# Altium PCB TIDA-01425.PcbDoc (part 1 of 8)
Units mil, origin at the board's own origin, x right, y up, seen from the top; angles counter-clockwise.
Board outline 7000 x 3600 mil, 6 copper layers (Layer 1 - Top Layer, Layer 2 - GND, Layer 3 - Signal / PWR, Layer 4 - Signal / PWR, Layer 5 - PWR, Layer 6 - Bottom Layer), stack 60.4 mil thick; 495 components, 307 nets, 2058 pads, 1870 vias.
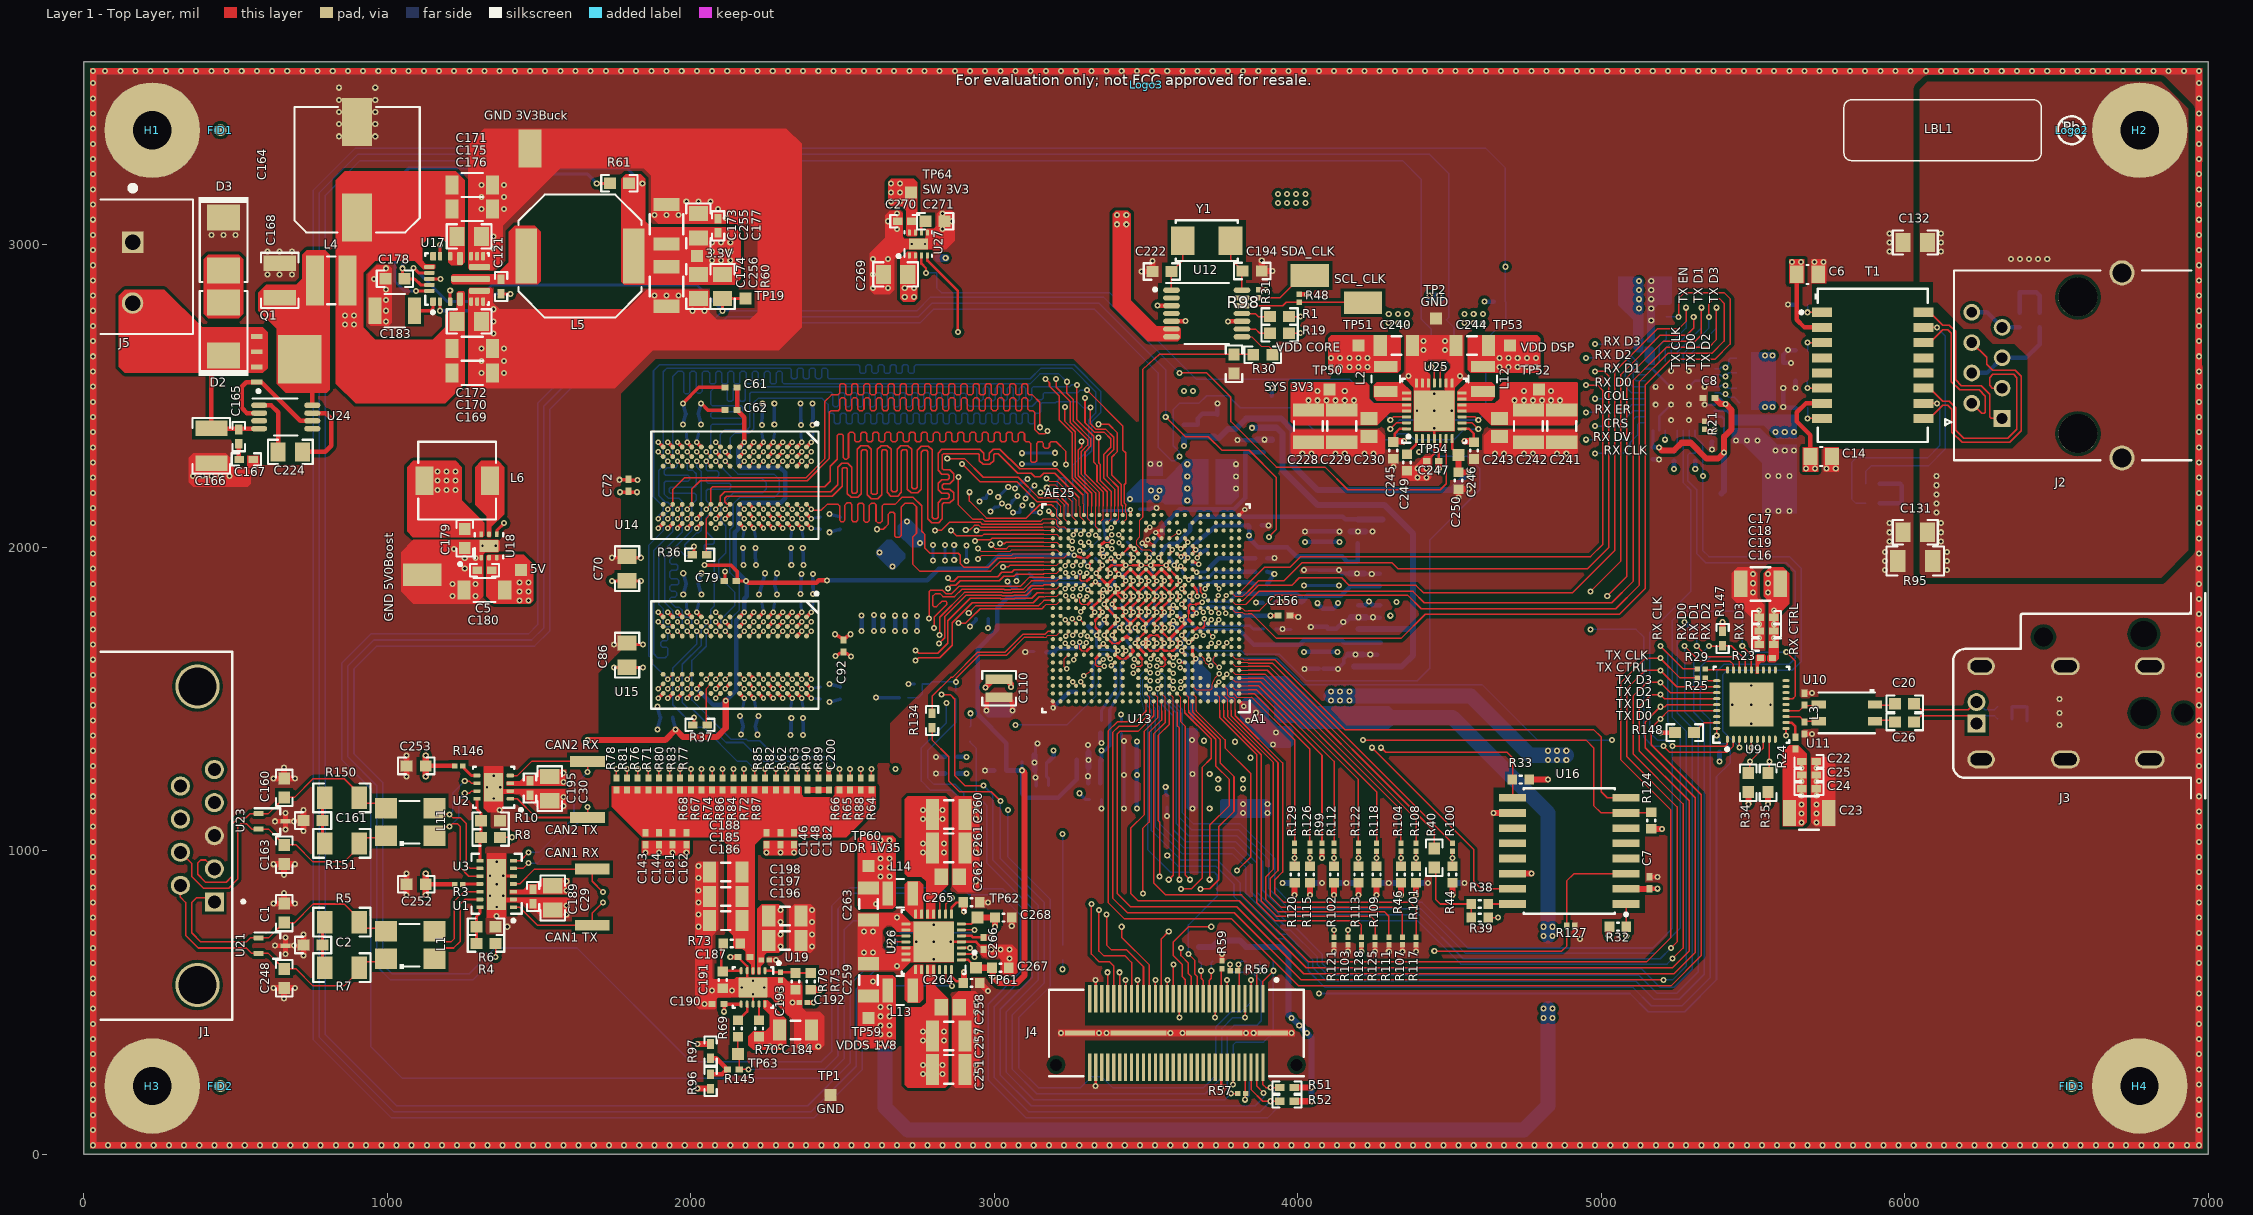
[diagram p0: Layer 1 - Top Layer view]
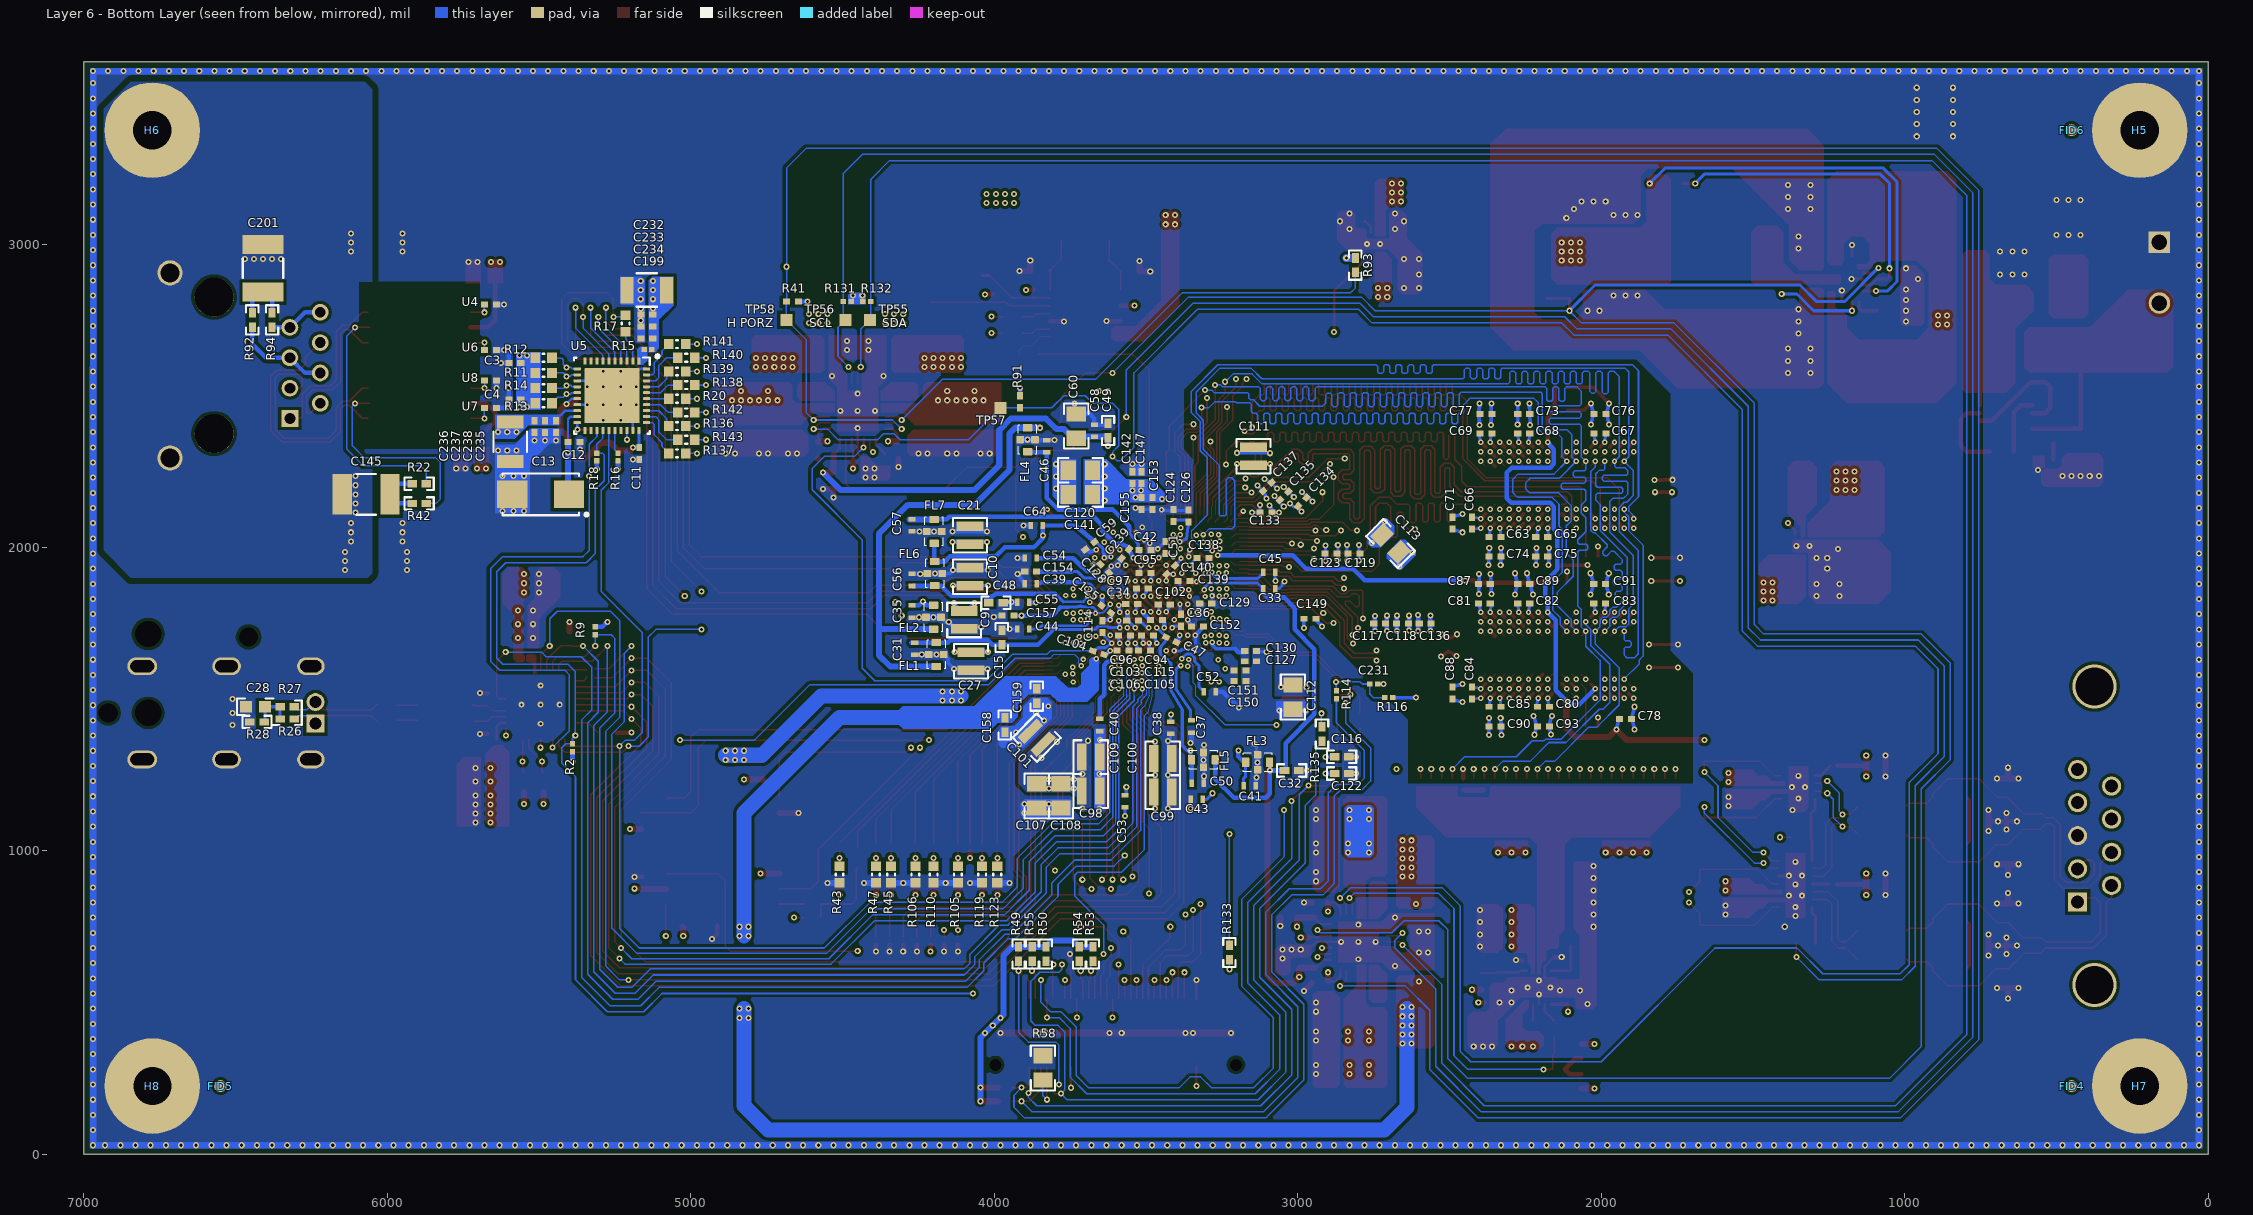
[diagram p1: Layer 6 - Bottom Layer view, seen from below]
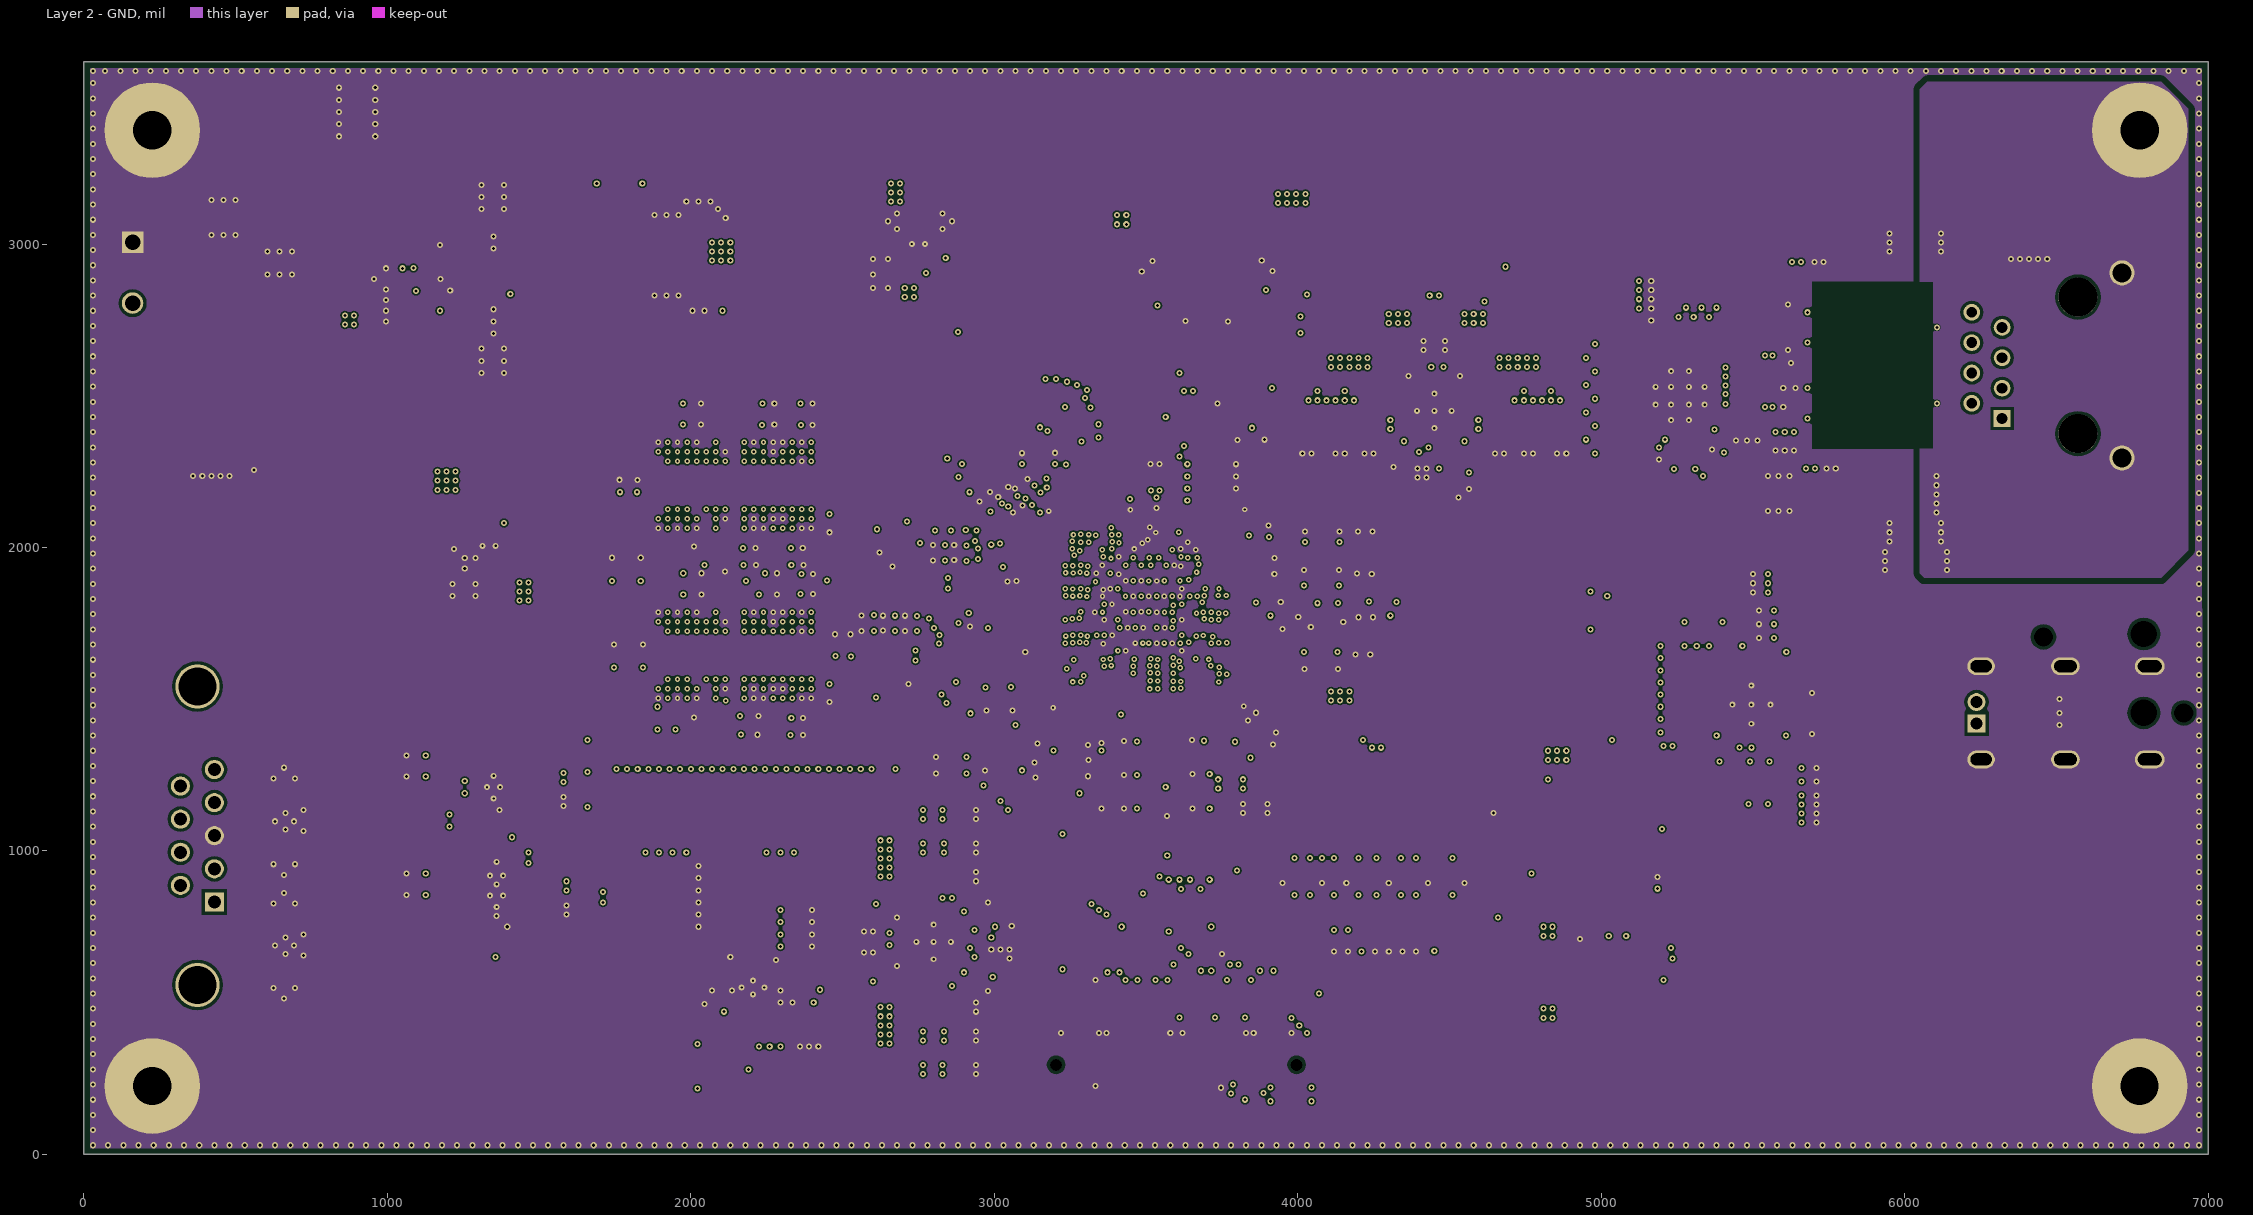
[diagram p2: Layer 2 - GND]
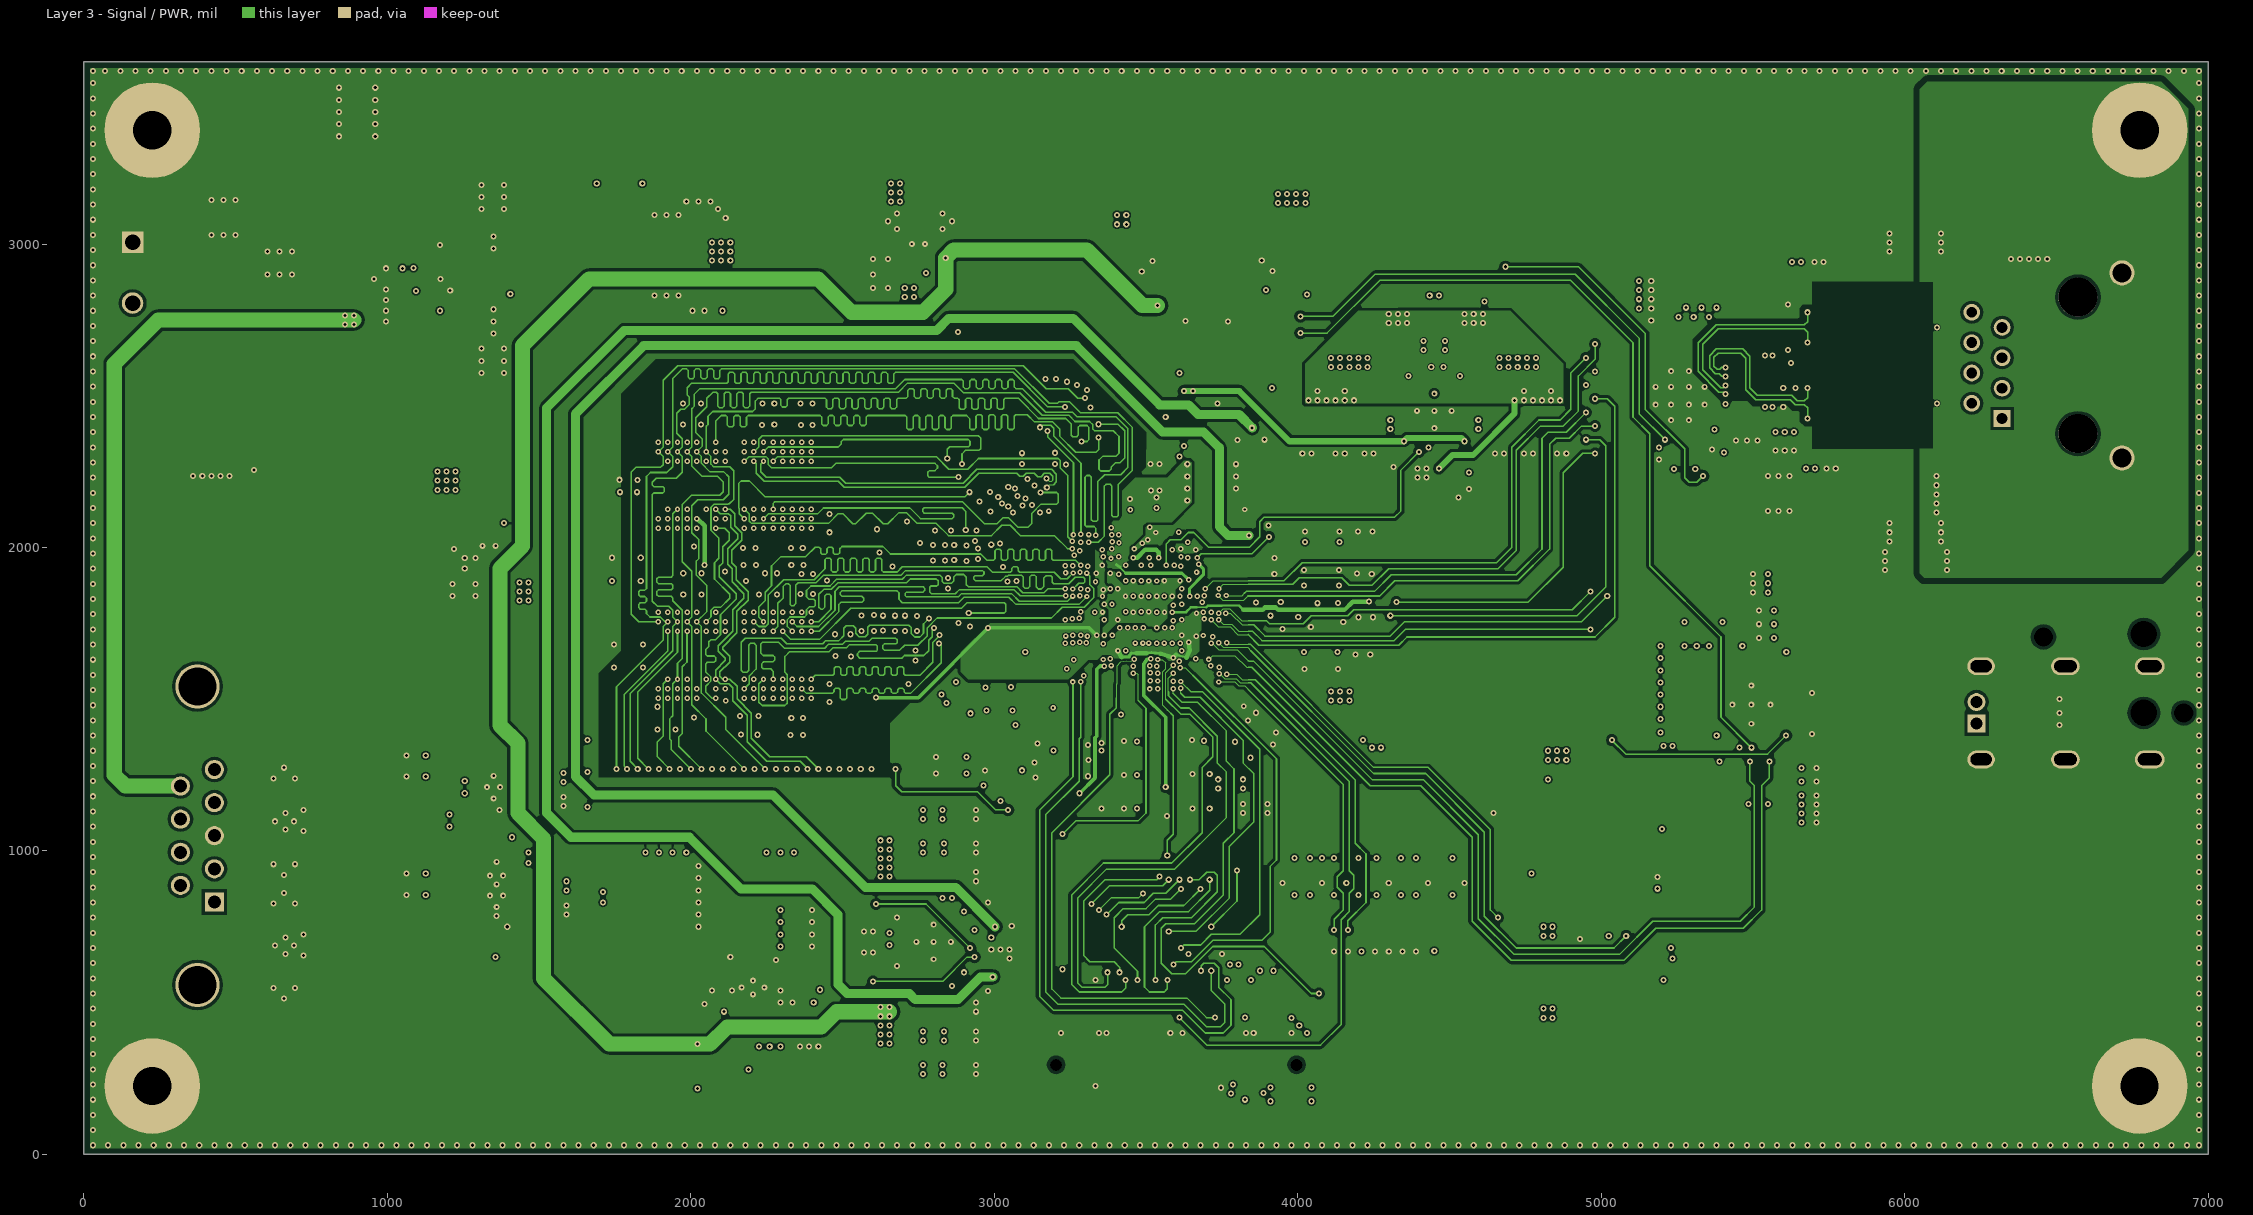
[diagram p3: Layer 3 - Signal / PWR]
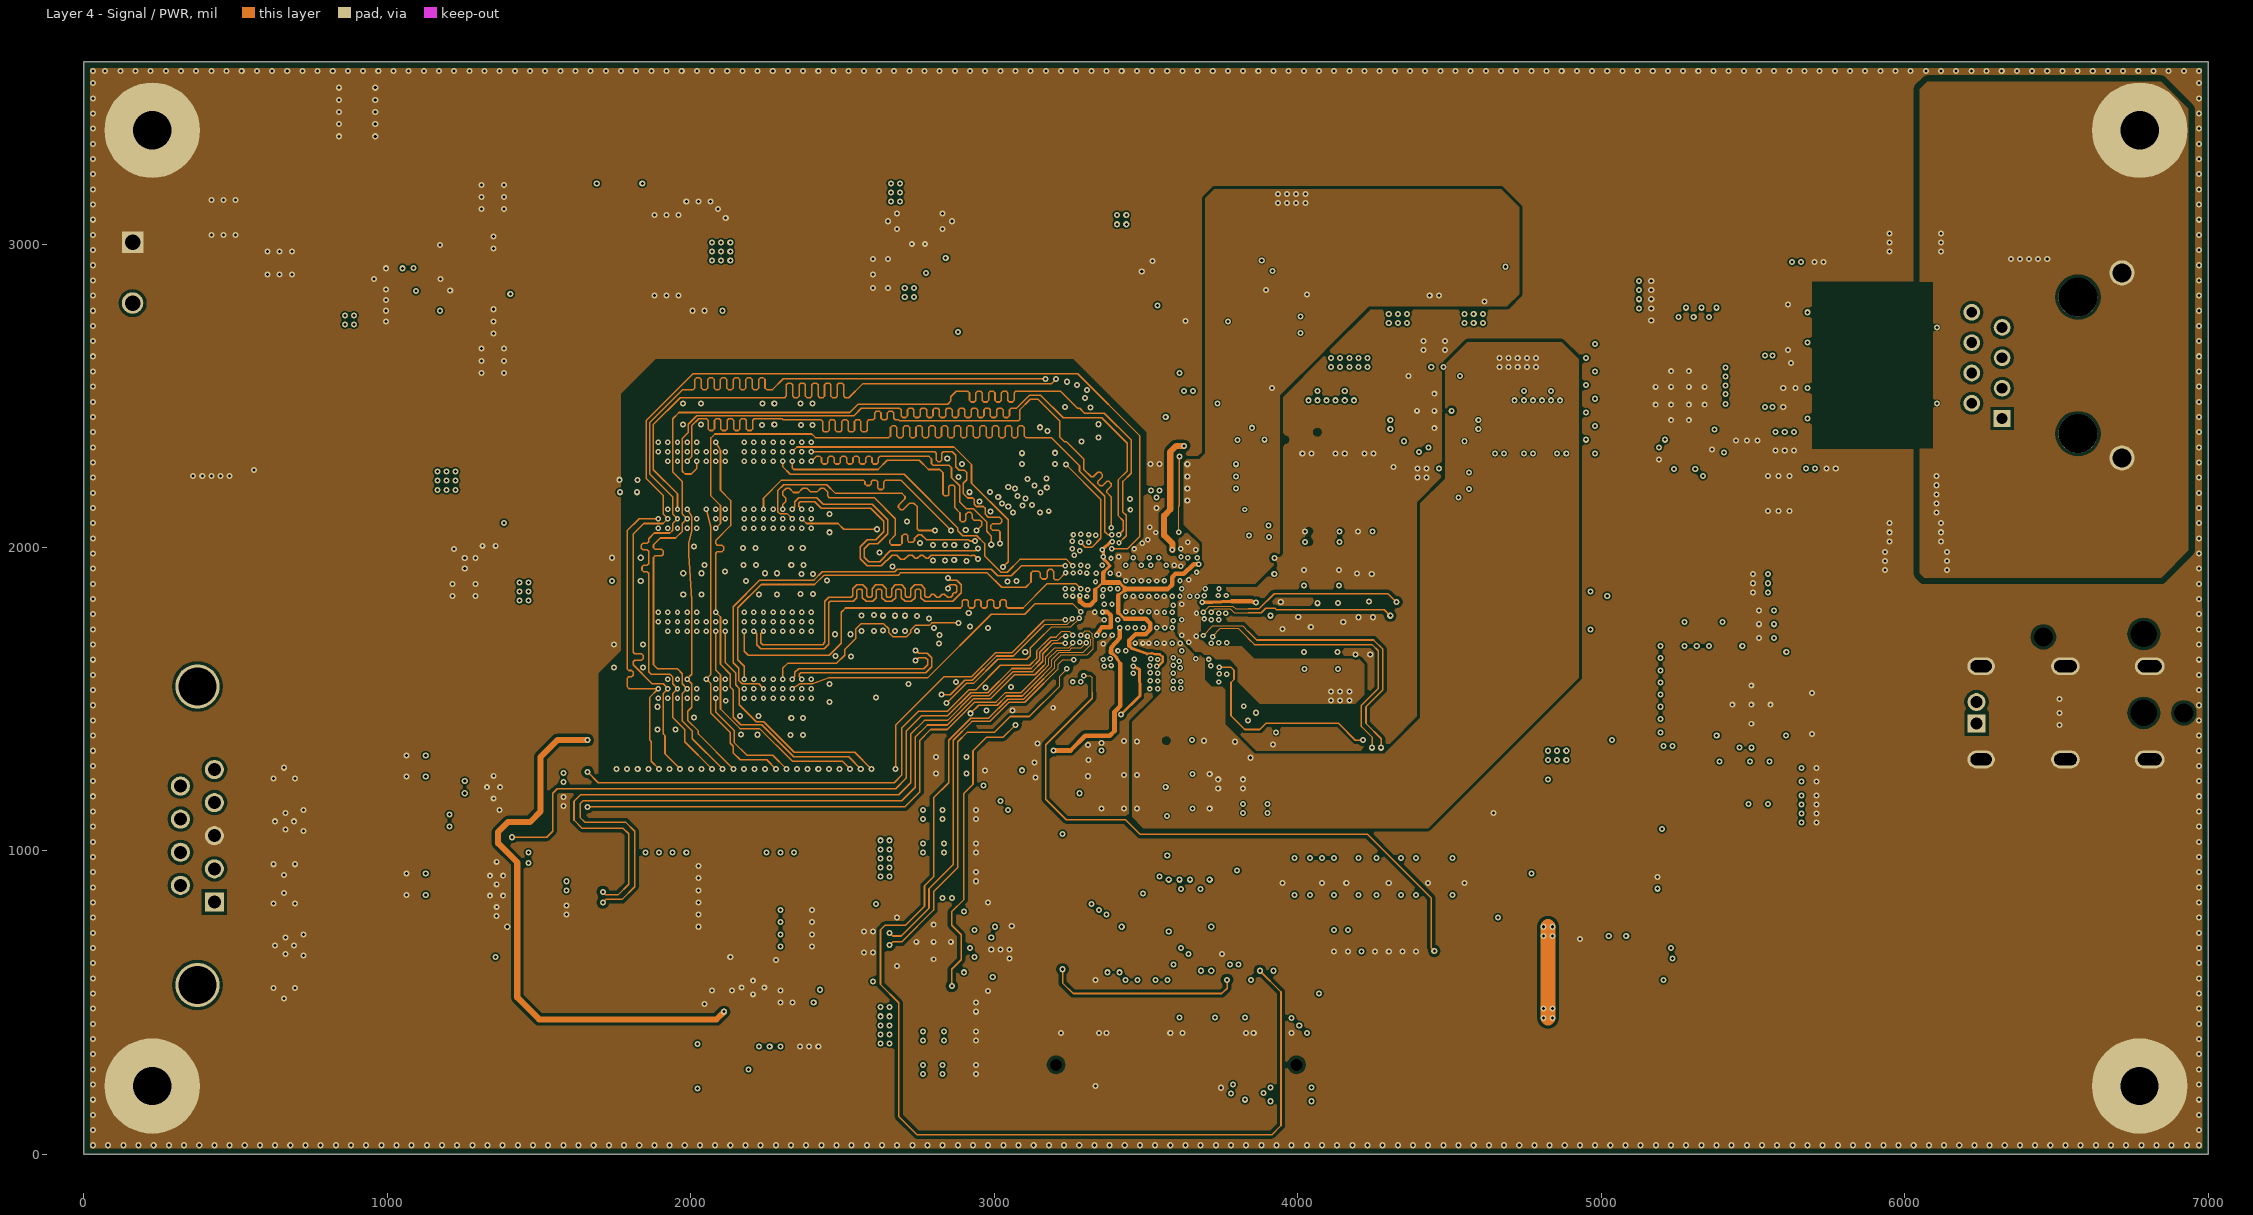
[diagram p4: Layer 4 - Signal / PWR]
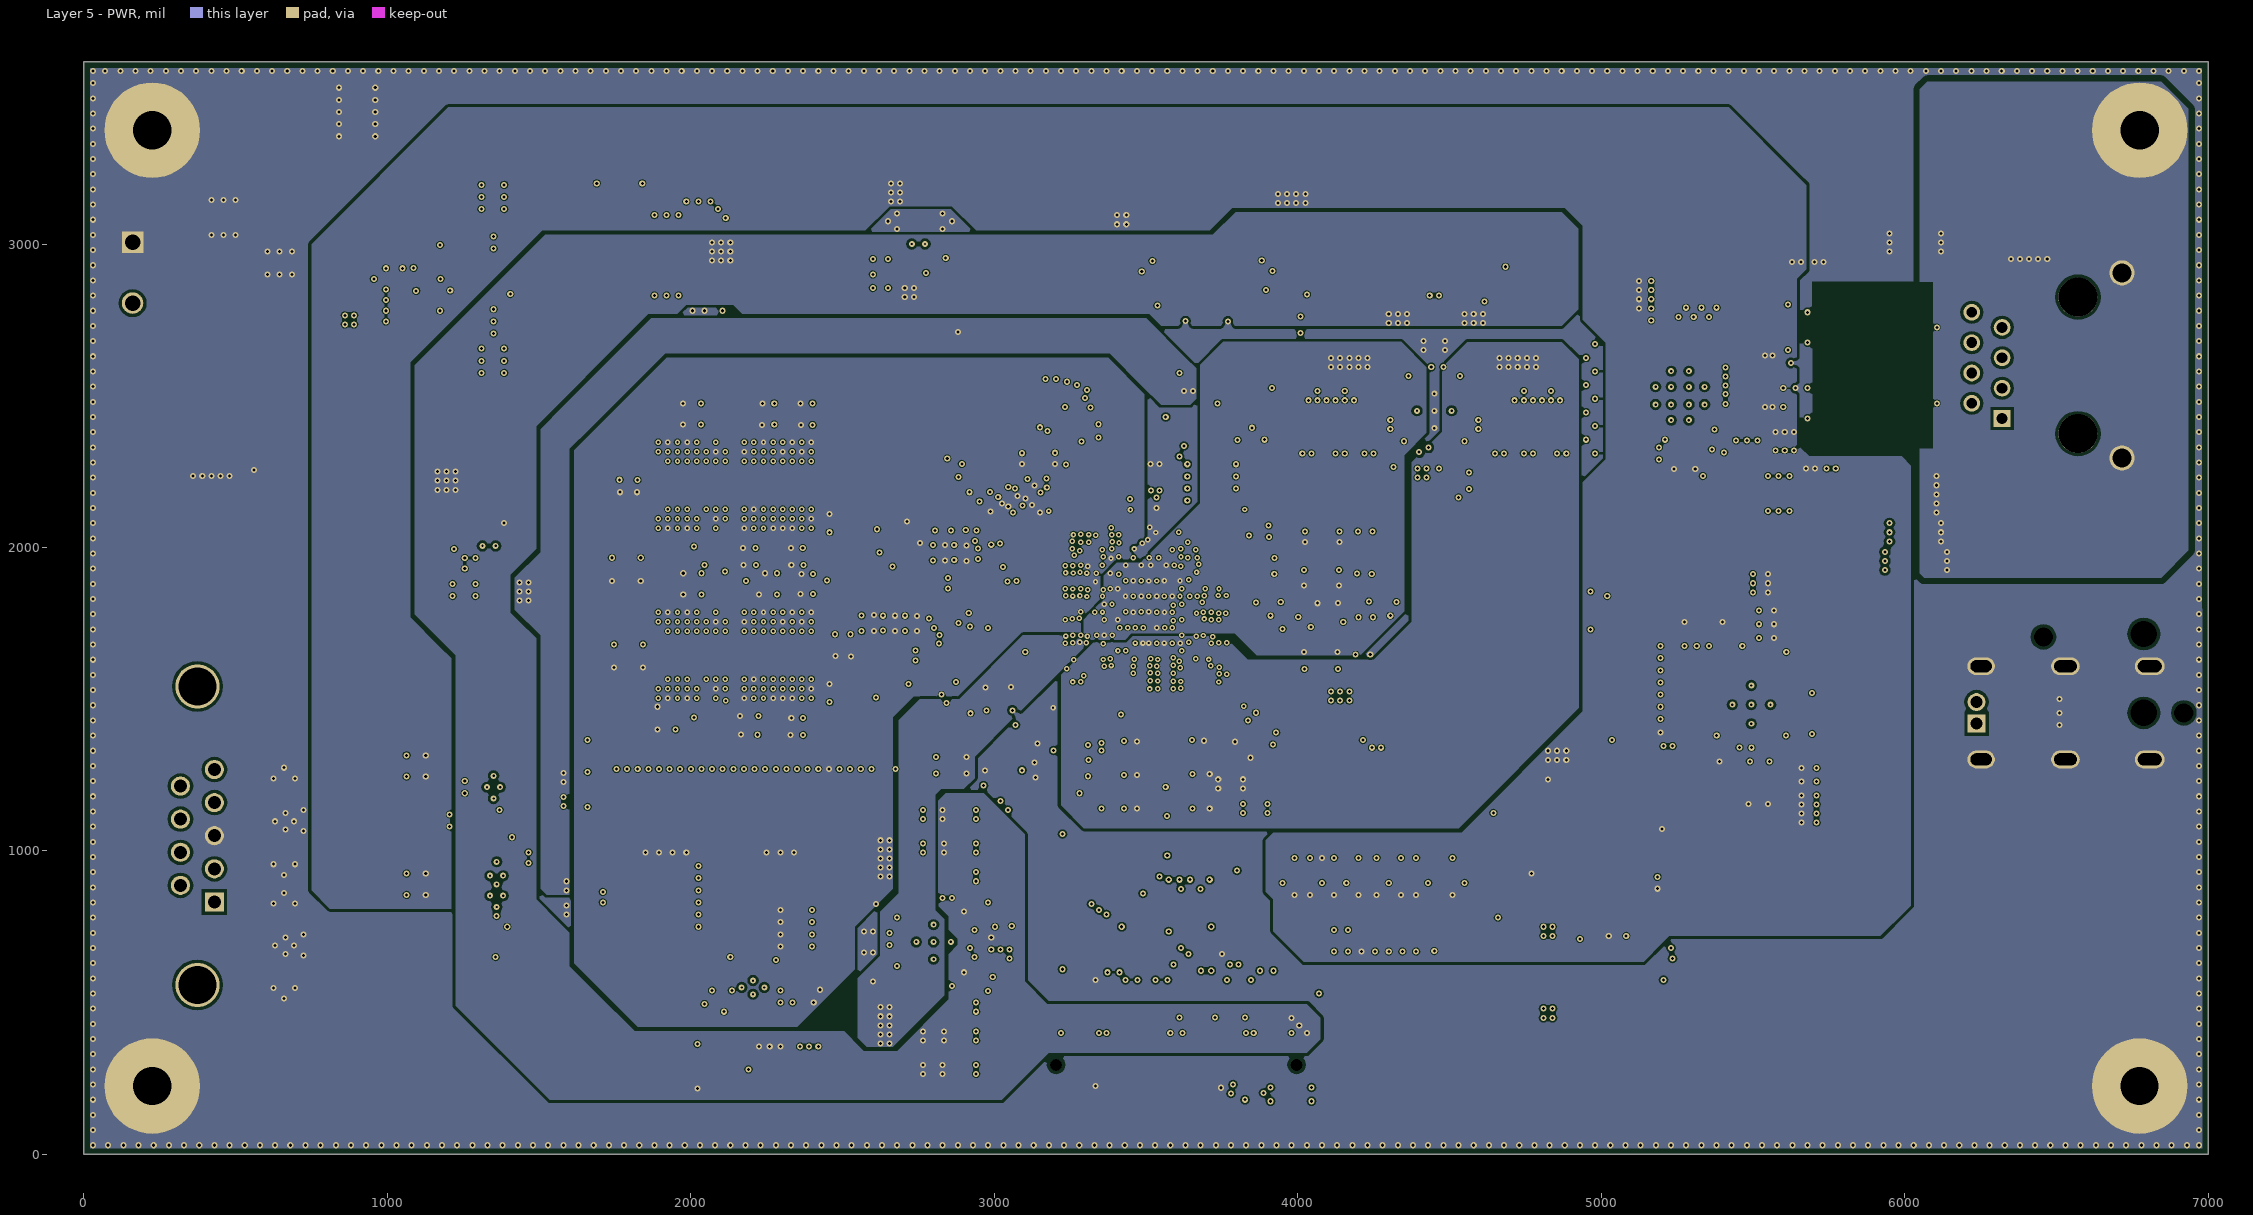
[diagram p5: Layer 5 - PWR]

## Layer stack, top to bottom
Top Solder: solder mask 0.5, Solder Resist, Dk 3.5
Layer 1 - Top Layer: signal copper 1.2
Dielectric 1: prepreg 3.4, 370H (1080HRC), Dk 4.2
Layer 2 - GND: signal copper 1.2
Dielectric 2: core 4.1, 370H (1-2116), Dk 4.2
Layer 3 - Signal / PWR: signal copper 0.6
Dielectric 3: prepreg 5.7, 370H (1080), Dk 4.2
Dielectric 4: core 28, 370H (4-7628), Dk 4.2
Dielectric 5: prepreg 5.7, 370H (1080), Dk 4.2
Layer 4 - Signal / PWR: signal copper 0.6
Dielectric 6: core 4.1, 370H (1-2116), Dk 4.2
Layer 5 - PWR: signal copper 1.2
Dielectric 7: prepreg 3.4, 370H (1080HRC), Dk 4.2
Layer 6 - Bottom Layer: signal copper 1.2
Bottom Solder: solder mask 0.5, Solder Resist, Dk 3.5

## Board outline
0,0 0,3600 7000,3600 7000,0

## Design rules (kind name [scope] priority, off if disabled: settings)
AcuteAngle [All] p1 off: minimum=4.50000000000000E+0001 checktracksonly=FALSE
AssemblyTestPointUsage [All] p1: valid=2
BoardOutlineClearance BoardOutlineClearance_MountingHoles [OnCopper and InComponentClass('Mounting Holes')] p1: gap=40 ignorepadtopadclearanceinfootprint=FALSE
BoardOutlineClearance BoardOutlineClearance_Poly [OnCopper and IsPoly] p2: gap=19 ignorepadtopadclearanceinfootprint=FALSE
BoardOutlineClearance [OnCopper and Not InComponentClass('Logo') and not InComponentClass('FiducialMark') and not InRegion(1000,500,4000,800) and not InPoly] p3: gap=19 ignorepadtopadclearanceinfootprint=FALSE
Clearance "Clearance_GND / RJ45_GND" [InNet('GND') vs InNet('RJ45 GND')] p1: gap=20 ignorepadtopadclearanceinfootprint=FALSE except(0: Arc-Hole Track-Hole SMDPad-Hole THPad-Hole Via-Hole Fill-Hole Poly-Hole Region-Hole Text-Hole)
Clearance Clearance_Poly_GND [InNet('GND') AND InPolygon] p2: gap=10 ignorepadtopadclearanceinfootprint=FALSE except(0: Arc-Hole Track-Hole SMDPad-Hole THPad-Hole Via-Hole Fill-Hole Poly-Hole Region-Hole Text-Hole)
Clearance Clearance_Keepouts [((IsTrack Or IsArc) And Not InPoly) And IsFree and IsKeepOut vs ((IsTrack Or IsArc) And Not InPoly) And IsFree and IsKeepOut] p3: gap=0 ignorepadtopadclearanceinfootprint=FALSE
Clearance Clearance_Poly [InPolygon] p4: gap=4 ignorepadtopadclearanceinfootprint=FALSE except(0: Arc-Hole Track-Hole SMDPad-Hole THPad-Hole Via-Hole Fill-Hole Poly-Hole Region-Hole Text-Hole; 8: Via-Poly; 10: Arc-Poly Track-Poly SMDPad-Poly THPad-Poly Fill-Poly Poly-Poly Poly-Region)
Clearance [All] p5: gap=3.75 ignorepadtopadclearanceinfootprint=FALSE except(0: Arc-Hole Track-Hole SMDPad-Hole THPad-Hole Via-Hole Fill-Hole Poly-Hole Region-Hole Text-Hole)
ComponentClearance "ComponentClearance_U1 / U3" [InComponent('U1') vs InComponent('U3')] p1: gap=0 collisioncheckmode=3 verticalgap=0 showdistances=FALSE
ComponentClearance ComponentClearance_MountingHoles_FiducialMarks [InComponentClass('Mounting Holes') vs InComponentClass('FiducialMark')] p2: gap=50 collisioncheckmode=3 verticalgap=10 showdistances=FALSE
ComponentClearance ComponentClearance_Shunt [InComponentClass('Header') vs InComponentClass('Shunt')] p3: gap=0 collisioncheckmode=3 verticalgap=0 showdistances=FALSE
ComponentClearance ComponentClearance_Logo [InComponentClass('Logo')] p4: gap=20 collisioncheckmode=3 verticalgap=10 showdistances=FALSE
ComponentClearance ComponentClearance_ScrewToNut [(HasFootprint('NY PMS 440 0025 PH')) vs (HasFootprint('Keystone_1902E'))] p5: gap=5 collisioncheckmode=3 verticalgap=10 showdistances=FALSE
ComponentClearance ComponentClearance_MountingHoles [InComponentClass('Mounting Holes')] p6: gap=40 collisioncheckmode=3 verticalgap=100000 showdistances=FALSE
ComponentClearance ComponentClearance_SmallPassives [HasFootprint('0201*') or HasFootprint('0402*') or HasFootprint('0508') or HasFootprint('0603*') or HasFootprint('0612') or HasFootprint('0805*') or HasFootprint('0815*') or HasFootprint('0830*') or HasFootprint('1206*') or HasFootprint('1210*') or HasFootprint('1808*') or HasFootprint('1812*') or HasFootprint('1825*') or HasFootprint('2010*') or HasFootprint('2220*') or HasFootprint('2225*') or HasFootprint('2512*') or HasFootprint('2728*') or HasFootprint('3518*') vs HasFootprint('0201*') or HasFootprint('0402*') or HasFootprint('0508') or HasFootprint('0603*') or HasFootprint('0612') or HasFootprint('0805*') or HasFootprint('0815*') or HasFootprint('0830*') or HasFootprint('1206*') or HasFootprint('1210*') or HasFootprint('1808*') or HasFootprint('1812*') or HasFootprint('1825*') or HasFootprint('2010*') or HasFootprint('2220*') or HasFootprint('2225*') or HasFootprint('2512*') or HasFootprint('2728*') or HasFootprint('3518*')] p7: gap=3.7 collisioncheckmode=3 verticalgap=10 showdistances=FALSE
ComponentClearance ComponentClearance_THtoSMT [IsThruComponent vs IsSMTComponent] p8: gap=20 collisioncheckmode=3 verticalgap=30 showdistances=FALSE
ComponentClearance ComponentClearance_THtoTH [IsThruComponent vs IsThruComponent] p9: gap=20 collisioncheckmode=3 verticalgap=30 showdistances=FALSE
ComponentClearance [All] p10: gap=3.7 collisioncheckmode=3 verticalgap=10 showdistances=FALSE
DiffPairsRouting [All] p1: maxlimit=100 minlimit=10 mostfreqgap=10 toplayer_minwidth=15 toplayer_maxwidth=15 toplayer_prefwidth=15 midlayer1_minwidth=15 midlayer1_maxwidth=15 midlayer1_prefwidth=15 midlayer2_minwidth=15 midlayer2_maxwidth=15 midlayer2_prefwidth=15 midlayer3_minwidth=15 midlayer3_maxwidth=15 midlayer3_prefwidth=15 midlayer4_minwidth=15 midlayer4_maxwidth=15 midlayer4_prefwidth=15 bottomlayer_minwidth=15 bottomlayer_maxwidth=15 bottomlayer_prefwidth=15 maxuncoupledlength=1000
FabricationTestPointUsage TestPointUsage [All] p1: valid=2 allowmultiple=FALSE
FabricationTestpoint Testpoint [All] p1: side=3 testpointundercomponent=TRUE minsize=40 maxsize=100 preferedsize=60 minholesize=0 maxholesize=40 preferedholesize=32 testpointgrid=1 allowsidetop=TRUE allowsidebottom=TRUE usegrid=TRUE gridtolerance=0.01
FanoutControl Fanout_LCC [IsLCC] p1: bgadir=Out bgaviamode=Centered fanoutstyle=Auto fanoutdirection=Alternating viagrid=1 // Fanout_LCC (Default Rule)
FanoutControl Fanout_BGA [IsBGA] p2: bgadir=Out bgaviamode=Centered fanoutstyle=Auto fanoutdirection=Alternating viagrid=1 // Fanout_BGA (Default Rule)
FanoutControl Fanout_Default [All] p4: bgadir=Out bgaviamode=Centered fanoutstyle=Auto fanoutdirection=Alternating viagrid=1 // Fanout_Default (Default Rule)
FanoutControl Fanout_Small [(CompPinCount < 5)] p5: bgadir=Out bgaviamode=Centered fanoutstyle=Auto fanoutdirection=OutThenIn viagrid=1 // Fanout_Small (Default Rule)
Height [All] p1: minheight=0 maxheight=1001 prefheight=500
HoleSize [All] p1: absolutevalues=TRUE maxlimit=251 minlimit=7.87 maxpercent=80.000 minpercent=20.000
MinimumAnnularRing MinimumAnnularRing_ThermalPadVias [IsVia and InAnyComponent] p1: minimumring=5.91
MinimumAnnularRing [All] p2 off: minimumring=5
MinimumSolderMaskSliver MinimumSolderMaskSliver_Logo [InComponentClass('Logo') vs InComponentClass('Logo')] p1: minsoldermaskwidth=0.7
MinimumSolderMaskSliver [All] p2: minsoldermaskwidth=0.9
PlaneConnect [All] p1: planeconnectstyle=Relief reliefexpansion=10 reliefentries=4 reliefconductorwidth=10 reliefairgap=10
PolygonConnect [All] p1: connectstyle=Direct reliefconductorwidth=10 reliefentries=4 polygonreliefangle="90 Angle" airgapwidth=10
RoutingVias ThermalPadVias [IsVia and InAnyComponent] p1: holewidth=7.87 width=19.68 viastyle="Through Hole" minholewidth=7.87 minwidth=19.68 maxholewidth=12.99 maxwidth=23.62
RoutingVias [All] p2: holewidth=16 width=20 viastyle="Through Hole" minholewidth=7.87 minwidth=18 maxholewidth=40 maxwidth=65
SilkToBoardRegionClearance [Not ((IsComment or IsDesignator) And (Hide <> 'False')) and not InRegion(1000,500,4000,800)] p1:
SilkToSilkClearance SilkToSilkClearance_Pb-FreeLogo [(HasFootprint('Pb-Free_Overlay_Medium') OR HasFootprint('Pb-Free_Overlay_Small')) vs (HasFootprint('Pb-Free_Overlay_Medium') OR HasFootprint('Pb-Free_Overlay_Small'))] p1: silktosilkclearance=0
SilkToSilkClearance [All] p2: silktosilkclearance=4
SilkToSolderMaskClearance "SilkToSolderMaskClearance_TI LOGO" [HasFootprint('TI_Stacked_Overlay_Small')] p1: minsilkscreentomaskgap=0 clearancetoexposedcopper=TRUE
SilkToSolderMaskClearance SilkToComponentPadClearance [(IsPad or IsFill or IsRegion) and InAnycomponent] p2 off: minsilkscreentomaskgap=3.5 clearancetoexposedcopper=TRUE
SilkToSolderMaskClearance "Silk to Solder Mask Opening" [All] p3 off: minsilkscreentomaskgap=4 clearancetoexposedcopper=FALSE
SolderMaskExpansion [All] p1: expansion=1.97
Width [All] p1: maxlimit=100 minlimit=4 preferedwidth=10 checkconnectedcopper=TRUE
14 further rules are at their usual default settings.

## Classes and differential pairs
component class JTAG: J4 R49 R50 R51 R52 R53 R54 R55 R56 R57 R58 R59
component class J6Entry: C7 C194 C222 C231 R1 R19 R30 R31 R32 R33 R38 R39 R40 R43 R44 R45 R46 R47 R48 R98 R99 R100 R101 R102 R103 R104 R105 R106 R107 R108 R109 R110 R111 R112 R113 R114 R115 R116 R117 R118 R119 R120 R121 R122 R123 R124 R125 R126 R127 R128 R129 R131 R132 R133 R134 R135 SCL_CLK SDA_CLK U12 U13 U16 Y1
component class "J6E DDR": C143 C144 C146 C148 C162 C181 C182 C184 C185 C186 C187 C188 C190 C191 C192 C193 C196 C197 C198 C200 R62 R63 R64 R65 R66 R67 R68 R69 R70 R71 R72 R73 R74 R75 R76 R77 R78 R79 R80 R81 R82 R83 R84 R85 R86 R87 R88 R89 R90 U19
component class Ethernet_subsystem: C3 C4 C6 C8 C11 C12 C13 C14 C16 C17 C18 C19 C20 C22 C23 C24 C25 C26 C28 C131 C132 C145 C199 C201 C232 C233 C234 C235 C236 C237 C238 J2 J3 L3 R2 R9 R11 R12 R13 R14 R15 R16 R17 R18 R20 R21 R22 R23 R24 R25 R26 R27 R28 R29 R34 R35 R42 R92 R94 R95 R136 R137 R138 R139 R140 R141 R142 R143 R147 R148 T1 U4 U5 U6 U7 U8 U9 U10 U11
component class "DIG PWR": C9 C10 C21 C27 C94 C95 C96 C97 C98 C99 C100 C101 C102 C103 C104 C105 C106 C107 C108 C109 C110 C111 C112 C113 C114 C115 C116 C117 C118 C119 C120 C122 C123 C124 C125 C126 C127 C128 C129 C130 C133 C134 C135 C136 C137 C138 C139 C140 C141 C142 C147 C149 C150 C151 C152 C153 C154 C155 C156 C157 C158 C159
component class DDR3: C61 C62 C63 C65 C66 C67 C68 C69 C70 C71 C72 C73 C74 C75 C76 C77 C78 C79 C80 C81 C82 C83 C84 C85 C86 C87 C88 C89 C90 C91 C92 C93 R36 R37 U14 U15
component class "DCDC PWR": 3.3V 5V C5 C121 C164 C165 C166 C167 C168 C169 C170 C171 C172 C173 C174 C175 C176 C177 C178 C179 C180 C183 C224 C255 C256 D2 D3 "GND 3V3Buck" "GND 5V0Boost" J5 L4 L5 L6 Q1 R60 R61 TP19 U17 U18 U24
component class CAN_subsystem2.0: C1 C2 C29 C30 C160 C161 C163 C189 C195 C248 C252 C253 "CAN1 RX" "CAN1 TX" "CAN2 RX" "CAN2 TX" J1 L1 L11 R3 R4 R5 R6 R7 R8 R10 R146 R150 R151 U1 U2 U3 U21 U23
component class "ANA PWR": C15 C31 C32 C33 C34 C35 C36 C37 C38 C39 C40 C41 C42 C43 C44 C45 C46 C47 C48 C49 C50 C51 C52 C53 C54 C55 C56 C57 C58 C59 C60 C64 C239 FL1 FL2 FL3 FL4 FL5 FL6 FL7
component class Label: LBL1
component class AssemblyNote: ZZ1 ZZ2 ZZ3 ZZ4
component class FiducialMark: FID1 FID2 FID3 FID4 FID5 FID6
component class TIDA-01425_EVM_Hardware: FID1 FID2 FID3 FID4 FID5 FID6 H1 H2 H3 H4 H5 H6 H7 H8 LBL1 Logo2 Logo3 ZZ1 ZZ2 ZZ3 ZZ4
component class "Mounting Holes": H1 H2 H3 H4
component class "LP873x (PMIC)": C228 C229 C230 C240 C241 C242 C243 C244 C245 C246 C247 C249 C250 C251 C257 C258 C259 C260 C261 C262 C263 C264 C265 C266 C267 C268 C269 C270 C271 L2 L12 L13 L14 R41 R91 R93 R96 R97 R145 TP1 TP2 TP50 TP51 TP52 TP53 TP54 TP55 TP56 TP57 TP58 TP59 TP60 TP61 TP62 TP63 TP64 U25 U26 U27

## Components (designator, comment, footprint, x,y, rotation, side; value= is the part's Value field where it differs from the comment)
3.3V "PAD_1MM_SQUARE" PAD_1MM_SQUARE 2020,2960 r90 top
5V "PAD_1MM_SQUARE" PAD_1MM_SQUARE 1440,1925 r90 top
C1 "GRM1885C1H560JA01D" 0603 660,795 r90 top value=56pF
C2 "GCM188R71H472KA37D" 0603 755,690 r180 top value=4700pF
C3 "0402ZC103KAT2A" 0402L 5580,2608 r0 bottom value=0.01uF
C4 "0402ZC103KAT2A" 0402L 5580,2488 r0 bottom value=0.01uF
C5 "GRM155R71C104JA88D" 0402 1320,1925 r180 top value=0.1uF
C6 "CEU4J2X7R1H104K125AE" 0805_150 5680,2900 r0 top value=0.1uF
C7 "0402ZC103KAT2A" 0402L 5160,895 r90 top value=0.01uF
C8 "C0402C104K4RACAUTO" 0402L 5355,2493 r0 top value=0.1uF
C9 "LLL219R70J105MA01L" 0508 4099,1761 r270 bottom value=1uF
C10 "LLL219R70J105MA01L" 0508 4080,1903 r90 bottom value=1uF
C11 "C0402C104K4RACAUTO" 0402L 5170,2310 r90 bottom value=0.1uF
C12 "C0402C104K4RACAUTO" 0402L 5385,2348 r0 bottom value=0.1uF
C13 "293D106X9010C2TE3" 6032-28 5495,2175 r0 bottom value=10uF
C14 "CEU4J2X7R1H104K125AE" 0805_150 5725,2300 r180 top value=0.1uF
C15 "GRM155R71C104KA88D" 0402 3975,1703 r90 bottom value=0.1uF
C16 "CGA2B2C0G1H101J050BA" 0402 5545,1680 r180 top value=100pF
C17 "CGA6P1X7R1E106M250AC" 1210_280 5525,1880 r180 top value=10uF
C18 "CGA2B3X7R1H103K050BB" 0402 5545,1770 r180 top value=0.01uF
C19 "CGA2B2C0G1H102J050BA" 0402 5545,1725 r180 top value=1000pF
C20 "06035C104KAT2A" 0603 6000,1485 r180 top value=0.1uF
C21 "LLL219R70J105MA01L" 0508 4080,2040 r90 bottom value=1uF
C22 "CGA2B2C0G1H101J050BA" 0402 5685,1295 r0 top value=100pF
C23 "CGA6P1X7R1E106M250AC" 1210_280 5685,1125 r0 top value=10uF
C24 "CGA2B3X7R1H103K050BB" 0402 5685,1205 r0 top value=0.01uF
C25 "CGA2B2C0G1H102J050BA" 0402 5685,1250 r0 top value=1000pF
C26 "06035C104KAT2A" 0603 6000,1425 r180 top value=0.1uF
C27 "LLL219R70J105MA01L" 0508 4077,1625 r270 bottom value=1uF
C28 "C0603C472K5RACTU" 0603 6435,1475 r0 bottom value=4700pF
C29 "C2012X7R1A475M125AC" 0805_HV 1545,845 r270 top value=4.7uF
C30 "C2012X7R1A475M125AC" 0805_HV 1535,1205 r270 top value=4.7uF
C31 "GCM155C71A105KE38D" 0402_070 4262,1666 r270 bottom value=1uF
C32 "GRM155R71C104KA88D" 0402 3020,1265 r180 bottom value=0.1uF
C33 "GCM155C71A105KE38D" 0402_070 3094,1864 r180 bottom value=1uF
C34 "GRM155R71C104KA88D" 0402L 3547,1813 r180 bottom value=0.1uF
C35 "GCM155C71A105KE38D" 0402_070 4271,1789 r270 bottom value=1uF
C36 "GRM155R71C104KA88D" 0402L 3385,1760 r90 bottom value=0.1uF
C37 "GCM155C71A105KE38D" 0402_070 3350,1410 r270 bottom value=1uF
C38 "GCM155C71A105KE38D" 0402_070 3418.35,1406 r270 bottom value=1uF
C39 "GCM155C71A105KE38D" 0402_070 3880,1880 r0 bottom value=1uF
C40 "GCM155C71A105KE38D" 0402_070 3652,1415 r270 bottom value=1uF
C41 "GCM155C71A105KE38D" 0402_070 3158,1215 r180 bottom value=1uF
C42 "GRM155R71C104KA88D" 0402L 3503,1992 r180 bottom value=0.1uF
C43 "GCM155C71A105KE38D" 0402_070 3333,1170 r0 bottom value=1uF
C44 "GCM155C71A105KE38D" 0402_070 3905,1731 r0 bottom value=1uF
C45 "GCM155C71A105KE38D" 0402_070 3094,1918 r180 bottom value=1uF
C46 "GCM155C71A105KE38D" 0402_070 3827,2334 r90 bottom value=1uF
C47 "GCM155C71A474KE36D" 0402L 3417,1696 r206 bottom value=0.47uF
C48 "GRM155R71C104KA88D" 0402 3994,1818 r180 bottom value=0.1uF
C49 "GRM155R71C104KA88D" 0402 3625,2385 r90 bottom value=0.1uF
C50 "GCM155C71A105KE38D" 0402_070 3329,1223 r180 bottom value=1uF
C51 "GRM155R71C104KA88D" 0402L 3436,2000 r90 bottom value=0.1uF
C52 "GCM155C71A105KE38D" 0402_070 3290,1524.65 r180 bottom value=1uF
C53 "GCM155C71A105KE38D" 0402_070 3569,1164 r270 bottom value=1uF
C54 "GCM155C71A105KE38D" 0402_070 3880,1965 r0 bottom value=1uF
C55 "GCM155C71A105KE38D" 0402_070 3905,1819 r0 bottom value=1uF
C56 "GCM155C71A105KE38D" 0402_070 4271,1893 r90 bottom value=1uF
C57 "GCM155C71A105KE38D" 0402_070 4271,2073 r270 bottom value=1uF
C58 "GCM155C71A105KE38D" 0402_070 3670,2385 r90 bottom value=1uF
C59 "GRM155R71C104KA88D" 0402L 3685,2005 r321 bottom value=0.1uF
C60 "GCM21BR71A106KE22L" 0805_HV 3730,2400 r90 bottom value=10uF
C61 "GCM155C71A474KE36D" 0402L 2132,2527 r0 top value=0.47uF
C62 "GCM155C71A474KE36D" 0402L 2132,2453 r180 top value=0.47uF
C63 "GCM155R71C104KA55D" 0402L 2350,2035 r0 bottom value=0.1uF
C64 "GCM155C71A105KE38D" 0402_070 3860,2072 r0 bottom value=1uF
C65 "GCM155R71C104KA55D" 0402L 2195.75,2035 r0 bottom value=0.1uF
C66 "GCM155R71C104KA55D" 0402L 2425,2080 r270 bottom value=0.1uF
C67 "GCM155R71C104KA55D" 0402L 2004.25,2375 r0 bottom value=0.1uF
C68 "GCM155R71C104KA55D" 0402L 2255,2375 r0 bottom value=0.1uF
C69 "GCM155R71C104KA55D" 0402L 2380,2375 r180 bottom value=0.1uF
C70 "LMK212BJ106KG-T" 0805_HV 1790,1930 r90 top value=10uF
C71 "GCM155C71A474KE36D" 0402L 2490,2080 r270 bottom value=0.47uF
C72 "GCM155C71A474KE36D" 0402L 1795,2205 r90 top value=0.47uF
C73 "GCM155C71A474KE36D" 0402L 2255,2440 r0 bottom value=0.47uF
C74 "GCM155C71A474KE36D" 0402L 2350,1970 r0 bottom value=0.47uF
C75 "GCM155C71A474KE36D" 0402L 2195.75,1970 r0 bottom value=0.47uF
C76 "GCM155C71A474KE36D" 0402L 2004.25,2440 r0 bottom value=0.47uF
C77 "GCM155C71A474KE36D" 0402L 2380,2440 r0 bottom value=0.47uF
C78 "GCM155C71A474KE36D" 0402L 1920,1435 r0 bottom value=0.47uF
C79 "GCM155C71A474KE36D" 0402L 2130,1890 r180 top value=0.47uF
C80 "GCM155R71C104KA55D" 0402L 2190,1475 r0 bottom value=0.1uF
C81 "GCM155R71C104KA55D" 0402L 2385,1815 r180 bottom value=0.1uF
C82 "GCM155R71C104KA55D" 0402L 2255,1815 r0 bottom value=0.1uF
C83 "GCM155R71C104KA55D" 0402L 2005,1815 r0 bottom value=0.1uF
C84 "GCM155R71C104KA55D" 0402L 2425,1520 r270 bottom value=0.1uF
C85 "GCM155R71C104KA55D" 0402L 2350,1475 r0 bottom value=0.1uF
C86 "LMK212BJ106KG-T" 0805_HV 1790,1645 r90 top value=10uF
C87 "GCM155C71A474KE36D" 0402L 2385,1880 r0 bottom value=0.47uF
C88 "GCM155C71A474KE36D" 0402L 2490,1520 r270 bottom value=0.47uF
C89 "GCM155C71A474KE36D" 0402L 2255,1880 r0 bottom value=0.47uF
C90 "GCM155C71A474KE36D" 0402L 2350,1410 r0 bottom value=0.47uF
C91 "GCM155C71A474KE36D" 0402L 2005,1880 r0 bottom value=0.47uF
C92 "GCM155C71A474KE36D" 0402L 2503,1675 r90 top value=0.47uF
C93 "GCM155C71A474KE36D" 0402L 2190,1410 r0 bottom value=0.47uF
C94 "GCM155C71A474KE36D" 0402L 3465,1761 r180 bottom value=0.47uF
C95 "GCM155C71A474KE36D" 0402L 3503,1916 r180 bottom value=0.47uF
C96 "GCM155C71A474KE36D" 0402L 3544,1760 r180 bottom value=0.47uF
C97 "GCM155C71A474KE36D" 0402L 3512,1864 r180 bottom value=0.47uF
C98 "LLL219R70J105MA01L" 0508 3682,1197 r180 bottom value=1uF
C99 "LLL219R70J105MA01L" 0508 3445,1194 r180 bottom value=1uF
C100 "LLL219R70J105MA01L" 0508 3445,1305 r180 bottom value=1uF
C101 "LLL219R70J105MA01L" 0508 3860,1373 r45 bottom value=1uF
C102 "GCM155C71A474KE36D" 0402L 3440,1812 r180 bottom value=0.47uF
C103 "GCM155C71A474KE36D" 0402L 3571,1710 r0 bottom value=0.47uF
C104 "GCM155C71A474KE36D" 0402L 3657,1653 r198 bottom value=0.47uF
C105 "GCM155C71A474KE36D" 0402L 3505,1660 r0 bottom value=0.47uF
C106 "GCM155C71A474KE36D" 0402L 3576,1660 r0 bottom value=0.47uF
C107 "GCM21BR71A106KE22L" 0805_HV 3860,1181 r270 bottom value=10uF
C108 "GCM21BR71A106KE22L" 0805_HV 3780,1181 r270 bottom value=10uF
C109 "LLL219R70J105MA01L" 0508 3682,1309 r180 bottom value=1uF
C110 "LLL219R70J105MA01L" 0508 3016,1536 r270 top value=1uF
C111 "LLL219R70J105MA01L" 0508 3146,2301 r90 bottom value=1uF
C112 "GCM21BR71A106KE22L" 0805_HV 3016,1507 r270 bottom value=10uF
C113 "GCM21BR71A106KE22L" 0805_HV 2694,2013 r225 bottom value=10uF
C114 "GCM155C71A474KE36D" 0402L 3643,1739 r90 bottom value=0.47uF
C115 "GCM155C71A474KE36D" 0402L 3495,1710 r180 bottom value=0.47uF
C116 "GCM155C71A474KE36D" 0402 2855,1310 r180 bottom value=0.47uF
C117 "GCM155C71A474KE36D" 0402L 2730,1750 r180 bottom value=0.47uF
C118 "GCM155C71A474KE36D" 0402L 2655,1750 r180 bottom value=0.47uF
C119 "GCM155C71A474KE36D" 0402L 2815,1980 r180 bottom value=0.47uF
C120 "GCM21BR71A106KE22L" 0805_HV 3716,2254.27 r0 bottom value=10uF
C121 "JMK105B7474KVHF" 0402 1374.72,2860 r270 top value=0.47uF
C122 "C1005X7S1A105K050BC" 0402 2855,1255 r180 bottom value=1uF
C123 "GCM155C71A474KE36D" 0402L 2890,1980 r180 bottom value=0.47uF
C124 "GRM155R71C104KA88D" 0402L 3410,2105 r90 bottom value=0.1uF
C125 "GRM155R71C104KA88D" 0402L 3631,1796.65 r218 bottom value=0.1uF
C126 "GRM155R71C104KA88D" 0402L 3360,2104 r90 bottom value=0.1uF
C127 "GRM155R71C104KA88D" 0402L 3155,1625 r180 bottom value=0.1uF
C128 "GRM155R71C104KA88D" 0402L 3636,1930 r226 bottom value=0.1uF
C129 "GRM155R71C104KA88D" 0402L 3303,1815 r0 bottom value=0.1uF
C130 "GRM155R71C104KA88D" 0402L 3155,1659 r180 bottom value=0.1uF
C131 "08055C472JAT2A" 0805_HV 6035,2050 r0 top value=4700pF
C132 "08055C472JAT2A" 0805_HV 6035,3005 r0 top value=4700pF
C133 "GCM155C71A474KE36D" 0402L 3105,2115 r180 bottom value=0.47uF
C134 "GCM155C71A474KE36D" 0402L 2985,2150 r135 bottom value=0.47uF
C135 "GCM155C71A474KE36D" 0402L 3045,2170 r135 bottom value=0.47uF
C136 "GCM155C71A474KE36D" 0402L 2580,1750 r180 bottom value=0.47uF
C137 "GCM155C71A474KE36D" 0402L 3100,2200 r135 bottom value=0.47uF
C138 "GCM155C71A474KE36D" 0402L 3312,1965 r0 bottom value=0.47uF
C139 "GCM155C71A474KE36D" 0402L 3375,1889 r0 bottom value=0.47uF
C140 "GCM155C71A474KE36D" 0402L 3418,1926 r315 bottom value=0.47uF
C141 "GRM21BR71C475KA73L" 0805_HV 3716,2174.27 r0 bottom value=4.7uF
C142 "GCM155C71A474KE36D" 0402L 3545,2230 r90 bottom value=0.47uF
C143 "GCM155C71A474KE36D" 0402L 1850,1040 r270 top value=0.47uF
C144 "GCM155C71A474KE36D" 0402L 1895,1040 r270 top value=0.47uF
C145 "1812GC102KA1" 1812_254 6070,2175 r0 bottom value=1000pF
C146 "GCM155C71A474KE36D" 0402L 2250,1040 r270 top value=0.47uF
C147 "C1005X7S1A105K050BC" 0402L 3515,2230 r90 bottom value=1uF
C148 "GCM155C71A474KE36D" 0402L 2295,1040 r270 top value=0.47uF
C149 "GRM155R71C104KA88D" 0402L 2960,1765 r180 bottom value=0.1uF
C150 "GRM155R71C104KA88D" 0402L 3190,1560 r180 bottom value=0.1uF
C151 "GRM155R71C104KA88D" 0402L 3190,1595 r180 bottom value=0.1uF
C152 "GRM155R71C104KA88D" 0402L 3330,1740 r0 bottom value=0.1uF
C153 "GRM155R71C104KA88D" 0402L 3479,2145 r270 bottom value=0.1uF
C154 "GRM155R71C104KA88D" 0402L 3880,1920 r0 bottom value=0.1uF
C155 "GRM155R71C104KA88D" 0402L 3515,2145 r270 bottom value=0.1uF
C156 "GRM155R71C104KA88D" 0402L 3955,1775 r0 top value=0.1uF
C157 "GRM155R71C104KA88D" 0402L 3955,1775 r0 bottom value=0.1uF
C158 "GRM155R71C104KA88D" 0402 3965,1415 r270 bottom value=0.1uF
C159 "GRM155R71C104KA88D" 0402 3860,1510 r270 bottom value=0.1uF
C160 "GRM1885C1H560JA01D" 0603 660,1207.6 r90 top value=56pF
C161 "GCM188R71H472KA37D" 0603 755,1100 r180 top value=4700pF
C162 "GCM155C71A474KE36D" 0402L 1985,1040 r270 top value=0.47uF
C163 "GRM1885C1H560JA01D" 0603 660,987.6 r270 top value=56pF
C164 "UUD1H151MNL1GS" SM_RADIAL_10BMM 900,3245 r90 top value=150uF
C165 "GRM155R71H472KA01D" 0402 510,2365 r270 top value=4700pF
C166 "GRM32ER71H106KA12L" 1210_270 420,2335 r270 top value=10uF
C167 "GRM155R71H472KA01D" 0402 535,2290 r180 top value=4700pF
C168 "GRM32NR71H684KA01L" 1210_150 645,2880 r90 top value=0.68uF
C169 "CL31B106KBHNNNE" 1206_180 1280,2575 r0 top value=10uF
C170 "C3216X7R1H475K160AC" 1206_180 1280,2655 r0 top value=4.7uF
C171 "CL31B106KBHNNNE" 1206_180 1279.72,3195 r0 top value=10uF
C172 "GRM21BR71H473KA01L" 0805_HV 1269.72,2745 r0 top value=0.047uF
C173 "C3225X7R1C226K250AC" 1210_280 1919.72,3065 r90 top value=22uF
C174 "C3225X7R1C226K250AC" 1210_280 1919.72,2860 r270 top value=22uF
C175 "C3216X7R1H475K160AC" 1206_180 1279.72,3115 r0 top value=4.7uF
C176 "GRM21BR71H473KA01L" 0805_HV 1269.72,3025 r0 top value=0.047uF
C177 "520L103KT16T" 0402_065 2089.72,3060 r90 top value=0.01uF
C178 "C1608X7R1E104K080AA" 0603 1025,2885 r180 top value=0.1uF
C179 "CGA3E1X7S1C225M080AC" 0603 1255,2030 r270 top value=2.2uF
C180 "GCM31CR71C475KA37L" 1206_180 1320,1860 r180 top value=4.7uF
C181 "GCM155C71A474KE36D" 0402L 1940,1040 r270 top value=0.47uF
C182 "GCM155C71A474KE36D" 0402L 2340,1040 r270 top value=0.47uF
C183 "1210ZC475KAT2A" 1210_280 1024.72,2780 r180 top value=4.7uF
C184 "CGA5L1X7R1C106K160AC" 1206_190L 2345,410 r0 top value=10uF
C185 "CGA5L1X7R1C106K160AC" 1206_190L 2115,850 r180 top value=10uF
C186 "CGA5L1X7R1C106K160AC" 1206_190L 2115,770 r180 top value=10uF
C187 "C0402C104K4RACAUTO" 0402L 2175,650 r180 top value=0.47uF
C188 "CGA5L1X7R1C106K160AC" 1206_190L 2115,930 r180 top value=10uF
C189 "GRM155R71C104KA88D" 0402 1480,850 r270 top value=0.1uF
C190 "C0402C104K4RACAUTO" 0402L 2090,495 r180 top value=0.47uF
C191 "CGA3E2C0G1H100D080AA" 0603L 2105,575 r270 top value=10pF
C192 "CGA1A2X7R1E102K030BA" 0201_033 2370,500 r180 top value=1000pF
C193 "CGA1A2X7R1E102K030BA" 0201_033 2295,587 r270 top value=1000pF
C194 "GRM1885C1H130JA01D" 0603 3850,2910.92 r0 top value=13pF
C195 "GRM155R71C104KA88D" 0402 1470,1207 r270 top value=0.1uF
C196 "CGA1A2X7R1E102K030BA" 0201_033 2245,640 r0 top value=1000pF
C197 "CGA5L1X7R1C106K160AC" 1206_190L 2310,705 r0 top value=10uF
C198 "CGA5L1X7R1C106K160AC" 1206_190L 2310,785 r0 top value=10uF
C199 "CGA2B2C0G1H101J050BA" 0402L 5145,2688 r0 bottom value=100pF
C200 "GCM155R71C104KA55D" 0402L 2455,1220 r270 top value=0.1uF
C201 "1812GC102KA1" 1812_254 6410,2920 r90 bottom value=1000pF
C222 "GRM1885C1H130JA01D" 0603 3552.5,2909.42 r180 top value=13pF
C224 "GRM21BR71C225KA12L" 0805_HV 680,2315 r180 top value=2.2uF
C228 "GRM32ER71C226KE18L" 1210_270L 4035,2400 r270 top value=22uF
C229 "GRM32ER71C226KE18L" 1210_270L 4145,2400 r270 top value=22uF
C230 "GCM21BR71A106KE22L" 0805L 4235,2395 r270 top value=10uF
C231 "CGA1A2X7R1E102K030BA" 0201_033 2750,1550 r180 bottom value=1000pF
C232 "CGA6P1X7R1E106M250AC" 1210_280 5145,2848 r0 bottom value=10uF
C233 "CGA2B3X7R1H103K050BB" 0402L 5145,2768 r0 bottom value=0.01uF
C234 "CGA2B2C0G1H102J050BA" 0402L 5145,2728 r0 bottom value=1000pF
C235 "CGA2B2C0G1H101J050BA" 0402L 5445,2398 r270 bottom value=100pF
C236 "CGA6P1X7R1E106M250AC" 1210_280 5595,2348 r270 bottom value=10uF
C237 "CGA2B3X7R1H103K050BB" 0402L 5515,2398 r270 bottom value=0.01uF
C238 "CGA2B2C0G1H102J050BA" 0402L 5480,2398 r270 bottom value=1000pF
C239 "GRM155R71C104KA88D" 0402L 3568,1979 r310 bottom value=0.1uF
C240 "GCM31CR71A226KE02" 1206_180L 4325,2665 r0 top value=22uF
C241 "GRM32ER71C226KE18L" 1210_270L 4870,2400 r270 top value=22uF
C242 "GRM32ER71C226KE18L" 1210_270L 4760,2400 r270 top value=22uF
C243 "GCM21BR71A106KE22L" 0805L 4665,2395 r270 top value=10uF
C244 "GCM31CR71A226KE02" 1206_180L 4575,2665 r180 top value=22uF
C245 "GRM188R71A225KE15D" 0603L 4315,2320 r270 top value=2.2uF
C246 "GRM188R71A225KE15D" 0603L 4581,2319 r270 top value=2.2uF
C247 "C1005X7R1E104M050BB" 0402L 4445,2285 r180 top value=0.1uF
C248 "GRM1885C1H560JA01D" 0603 660,580 r270 top value=56pF
C249 "GCM188R71C105KA64D" 0603L 4360,2280 r270 top value=1uF
C250 "GCM188R71C105KA64D" 0603L 4530,2220 r270 top value=1uF
C251 "GRM32ER71C226KE18L" 1210_270L 2850,280 r0 top value=22uF
C252 "06033C104JAT2A" 0603 1095,890 r180 top value=0.1uF
C253 "06033C104JAT2A" 0603 1095,1280 r180 top value=0.1uF
C255 "EMK212BB7106MG-T" 0805_HV 2024.72,3060 r90 top value=10uF
C256 "EMK212BB7106MG-T" 0805_HV 2024.72,2860 r270 top value=10uF
C257 "GRM32ER71C226KE18L" 1210_270L 2850,390 r0 top value=22uF
C258 "GCM21BR71A106KE22L" 0805L 2855,485 r0 top value=10uF
C259 "GCM31CR71A226KE02" 1206_180L 2585,575 r90 top value=22uF
C260 "GRM32ER71C226KE18L" 1210_270L 2850,1120 r0 top value=22uF
C261 "GRM32ER71C226KE18L" 1210_270L 2850,1010 r0 top value=22uF
C262 "GCM21BR71A106KE22L" 0805L 2855,915 r0 top value=10uF
C263 "GCM31CR71A226KE02" 1206_180L 2585,825 r270 top value=22uF
C264 "GRM188R71A225KE15D" 0603L 2925,565 r0 top value=2.2uF
C265 "GRM188R71A225KE15D" 0603L 2925,831 r0 top value=2.2uF
C266 "C1005X7R1E104M050BB" 0402L 2965,695 r270 top value=0.1uF
C267 "GCM188R71C105KA64D" 0603L 3020,615 r0 top value=1uF
C268 "GCM188R71C105KA64D" 0603L 3030,780 r0 top value=1uF
C269 "GCM21BR71C475KA73L" 0805_HV 2675,2900 r180 top value=4.7uF
C270 "C0402C104K4RACAUTO" 0402 2705,3075 r180 top value=0.1uF
C271 "06035A221FAT2A" 0603 2805,3075 r0 top value=220pF
"CAN1 RX" "TESTPOINT" PAD_2-92x0-9MM_SMD 1675,940 r0 top
"CAN1 TX" "TESTPOINT" PAD_2-92x0-9MM_SMD 1675,755 r0 top
"CAN2 RX" "TESTPOINT" PAD_2-92x0-9MM_SMD 1660,1295 r0 top
"CAN2 TX" "TESTPOINT" PAD_2-92x0-9MM_SMD 1660,1110 r180 top
D2 "SMBJ26A-13-F" SMB 460,2720 r90 top value=26V
D3 "SMBJ14A-13-F" SMB 460,3000 r270 top value=14V
FID1 "Fiducial" Fiducial10-20 450,3375 r0 top
FID2 "Fiducial" Fiducial10-20 450,225 r0 top
FID3 "Fiducial" Fiducial10-20 6550,225 r0 top
FID4 "Fiducial" Fiducial10-20 450,225 r180 bottom
FID5 "Fiducial" Fiducial10-20 6550,225 r180 bottom
FID6 "Fiducial" Fiducial10-20 450,3375 r180 bottom
FL1 "NFM21PC474R1C3D" Murata_NFM21PC 4191,1647 r90 bottom value=0.47uF
FL2 "NFM21PC474R1C3D" Murata_NFM21PC 4200,1770 r90 bottom value=0.47uF
FL3 "NFM21PC474R1C3D" Murata_NFM21PC 3132,1292 r0 bottom value=0.47uF
FL4 "NFM21PC474R1C3D" Murata_NFM21PC 3890,2355 r270 bottom value=0.47uF
FL5 "NFM21PC474R1C3D" Murata_NFM21PC 3311,1300 r0 bottom value=0.47uF
FL6 "NFM21PC474R1C3D" Murata_NFM21PC 4196,1914 r270 bottom value=0.47uF
FL7 "NFM21PC474R1C3D" Murata_NFM21PC 4198,2053 r90 bottom value=0.47uF
"GND 3V3Buck" "PAD_3.2x1.9MM_SMD" PAD_3-2x1-9MM_SMD 1470,3315 r90 top
"GND 5V0Boost" "PAD_3.2x1.9MM_SMD" PAD_3-2x1-9MM_SMD 1115,1910 r180 top
H1 "NY PMS 440 0025 PH" "NY PMS 440 0025 PH" 225,3375 r0 top locked
H2 "NY PMS 440 0025 PH" "NY PMS 440 0025 PH" 6775,3375 r0 top locked
H3 "NY PMS 440 0025 PH" "NY PMS 440 0025 PH" 225,225 r0 top locked
H4 "NY PMS 440 0025 PH" "NY PMS 440 0025 PH" 6774.47,225 r0 top locked
H5 "1902E" Keystone_1902E 225,3375 r180 bottom locked
H6 "1902E" Keystone_1902E 6775,3375 r180 bottom locked
H7 "1902E" Keystone_1902E 225,225 r180 bottom locked
H8 "1902E" Keystone_1902E 6774.47,225 r180 bottom locked
J1 "1734354-1" TE_1734354-1 0,1050 r180 top
J2 "ARJ012-110553" Abracon_ARJ012-110553 7000,2600 r90 top locked
J3 "0-2290024-1" TE_1PORT_B1-B 6920,1455 r90 top
J4 "QSH-030-01-L-D-A" Samtec_QSH-030-01-X-D-A 3600,400 r270 top locked
J5 "OSTTA024163" On-Shore_OSTTA024163 180,2925 r270 top
L1 "B82789C0104N002" SIMDAD_1812 1075,690 r90 top value=100uH
L2 "DFE252012PD-R47M" DFE252012P 4290,2555 r90 top value=470nH
L3 "DLW43MH201XK2L" MuRata_DLW43MH 5810,1455 r270 top value=200uH
L4 "SRN4012TA-1R0M" SRN4012TA 815,2880 r0 top value=1uH
L5 "7440650022" WE-TPC-XLH2 1634.72,2960 r0 top value=2.2uH
L6 "B82462G4222M" B82462G4 1230,2220 r0 top value=2.2uH
L11 "B82789C0104N002" SIMDAD_1812 1075,1095 r90 top value=100uH
L12 "DFE252012PD-R47M" DFE252012P 4610,2555 r90 top value=470nH
L13 "DFE252012PD-R47M" DFE252012P 2690,540 r180 top value=470nH
L14 "DFE252012PD-R47M" DFE252012P 2690,860 r180 top value=470nH
LBL1 "Size: 0.65\" x 0.20 \"" Label_650x200 6125,3375 r0 top
Logo2 "Pb-Free Symbol" Pb-Free_Overlay_Small 6550,3375 r0 top
Logo3 "FCC disclaimer" FCC_disclaimer 3500,3525 r0 top
Q1 "SQJ422EP-T1-GE3" PowerPAK_SO-8L 680,2620 r0 top value=40V
R1 "RC0603FR-0733RL" 0603 3940,2760.92 r0 top value=33.0
R2 "RC0201FR-072K49L" 0201 5390,1340 r270 bottom value=2.49k
R3 "CRCW02010000Z0ED" 0201 1235,890 r180 top value=0
R4 "ERJ-3GEY0R00V" 0603 1325,695 r0 top value=0
R5 "CRCW120660R4FKEA" 1206 850,765 r0 top value=60.4
R6 "RCG060310K0FKEA" 0603 1325,750 r180 top value=10.0k
R7 "CRCW120660R4FKEA" 1206 850,615 r180 top value=60.4
R8 "ERJ-3GEY0R00V" 0603 1340,1044 r0 top value=0
R9 "RC0201FR-072K49L" 0201 5315,1725 r90 bottom value=2.49k
R10 "RCG060310K0FKEA" 0603 1340,1098.9 r180 top value=10.0k
R11 "CRCW060349R9FKEA" 0603L 5485,2575 r0 bottom value=49.9
R12 "CRCW060349R9FKEA" 0603L 5485,2625 r180 bottom value=49.9
R13 "CRCW060349R9FKEA" 0603L 5485,2475 r0 bottom value=49.9
R14 "CRCW060349R9FKEA" 0603L 5485,2525 r180 bottom value=49.9
R15 "CRCW02010000Z0ED" 0201 5141,2653 r0 bottom value=0
R16 "CRCW02010000Z0ED" 0201 5240,2298 r90 bottom value=0
R17 "CRCW060349R9FKEA" 0603L 5215,2738 r270 bottom value=49.9
R18 "RC0201FR-072K49L" 0201 5310,2298 r270 bottom value=2.49k
R19 "RC0603FR-0733RL" 0603 3940,2705.92 r0 top value=33.0
R20 "CRCW060349R9FKEA" 0603L 5045,2490 r0 bottom value=49.9
R21 "RC0201FR-074K87L" 0201 5340,2402.84 r90 top value=4.87k
R22 "CRCW040275R0FKED" 0402 5895,2210 r180 bottom value=75.0
R23 "CRCW04020000Z0ED" 0402L 5545,1635 r180 top value=0
R24 "CRCW04020000Z0ED" 0402L 5640,1355 r90 top value=0
R25 "CRCW02010000Z0ED" 0201 5330,1570 r0 top value=0
R26 "ERJ-2RKF2001X" 0402 6330,1435 r180 bottom value=2.00k
R27 "ERJ-2RKF2001X" 0402 6330,1475 r180 bottom value=2.00k
R28 "CRCW0402100KFKED" 0402 6430,1425 r180 bottom value=100k
R29 "CRCW02010000Z0ED" 0201 5330,1600 r0 top value=0
R30 "RC0603FR-0768RL" 0603 3885,2635 r180 top value=68.0
R31 "RC0201FR-074K99L" 0201 3870,2835.92 r90 top value=4.99k
R32 "RCG060310K0FKEA" 0603L 5055,750 r180 top value=10.0k
R33 "RCG060310K0FKEA" 0603L 4735,1235 r0 top value=10.0k
R34 "RCG060310K0FKEA" 0603 5485,1225 r90 top value=10.0k
R35 "RCG060310K0FKEA" 0603 5550,1225 r90 top value=10.0k
R36 "ERJ-2RKF2400X" 0402 2029,1976 r0 top value=240
R37 "ERJ-2RKF2400X" 0402 2030,1415 r0 top value=240
R38 "CRCW060310R0FKEA" 0603L 4600,825 r180 top value=10.0
R39 "CRCW060310R0FKEA" 0603L 4600,780 r180 top value=10.0
R40 "ERJ-3GEY0R00V" 0603 4450,977.01 r90 top value=0
R41 "MCR01MRTF1002" 0402L 4665,2810 r180 bottom value=10.0k
R42 "CRCW040275R0FKED" 0402 5895,2145 r180 bottom value=75.0
R43 "RMCF0603ZT0R00" 0603L 4510,922.01 r270 bottom value=0
R44 "RMCF0603ZT0R00" 0603L 4510,922.01 r270 top value=0
R45 "RMCF0603ZT0R00" 0603L 4340,922.01 r270 bottom value=0
R46 "RMCF0603ZT0R00" 0603L 4340,922.01 r270 top value=0
R47 "RMCF0603ZT0R00" 0603L 4390,922.01 r270 bottom value=0
R48 "RC0201FR-074K99L" 0201 4005,2820.92 r90 top value=4.99k
R49 "MCR01MZPF1000" 0402 3920,660 r90 bottom value=100
R50 "CRG0402F4K7" 0402 3830,660 r90 bottom value=4.70k
R51 "CRG0402F4K7" 0402 3965,220 r0 top value=4.70k
R52 "CRG0402F4K7" 0402 3965,175 r0 top value=4.70k
R53 "CRG0402F4K7" 0402 3675,660 r90 bottom value=4.70k
R54 "CRG0402F4K7" 0402 3720,660 r90 bottom value=4.70k
R55 "CRG0402F4K7" 0402 3875,660 r90 bottom value=4.70k
R56 "CRCW02010000Z0ED" 0201 3790,605 r0 top value=0
R57 "CRCW02010000Z0ED" 0201 3815,200 r0 top value=0
R58 "CRCW08054K75FKEA" 0805_HV 3840,285 r270 bottom value=4.75k
R59 "CRCW02010000Z0ED" 0201 3750,625 r270 top value=0
R60 "RR1220P-104-D" 0805_HV 2104.72,2860 r90 top value=100k
R61 "CRCW06033R00JNEA" 0603 1764.72,3200 r0 top value=3.0
R62 "CRCW040249R9FKED" 0402L 2315,1220 r270 top value=49.9
R63 "CRCW040249R9FKED" 0402L 2350,1220 r270 top value=49.9
R64 "CRCW040249R9FKED" 0402L 2595,1220 r90 top value=49.9
R65 "CRCW040249R9FKED" 0402L 2525,1220 r90 top value=49.9
R66 "CRCW040249R9FKED" 0402L 2490,1220 r270 top value=49.9
R67 "CRCW040249R9FKED" 0402L 2035,1220 r270 top value=49.9
R68 "CRCW040249R9FKED" 0402L 2000,1220 r270 top value=49.9
R69 "RCG060310K0FKEA" 0603L 2155,415 r270 top value=10.0k
R70 "RC0603FR-07100KL" 0603L 2225,415 r270 top value=100k
R71 "CRCW040249R9FKED" 0402L 1860,1220 r270 top value=49.9
R72 "CRCW040249R9FKED" 0402L 2175,1220 r270 top value=49.9
R73 "CRCW060310R0FKEA" 0603L 2135,695 r0 top value=10.0
R74 "CRCW040249R9FKED" 0402L 2070,1220 r270 top value=49.9
R75 "CRCW060310K0FKEA" 0603L 2395,570 r90 top value=10.0k
R76 "CRCW040249R9FKED" 0402L 1825,1220 r270 top value=49.9
R77 "CRCW040249R9FKED" 0402L 1965,1220 r270 top value=49.9
R78 "CRCW040249R9FKED" 0402L 1755,1220 r270 top value=49.9
R79 "CRCW060310K0FKEA" 0603L 2345,570 r270 top value=10.0k
R80 "CRCW040249R9FKED" 0402L 1895,1220 r270 top value=49.9
R81 "CRCW040249R9FKED" 0402L 1790,1220 r270 top value=49.9
R82 "CRCW040249R9FKED" 0402L 2280,1220 r270 top value=49.9
R83 "CRCW040249R9FKED" 0402L 1930,1220 r270 top value=49.9
R84 "CRCW040249R9FKED" 0402L 2140,1220 r270 top value=49.9
R85 "CRCW040249R9FKED" 0402L 2245,1220 r270 top value=49.9
R86 "CRCW040249R9FKED" 0402L 2105,1220 r270 top value=49.9
R87 "CRCW040249R9FKED" 0402L 2210,1220 r270 top value=49.9
R88 "CRCW040249R9FKED" 0402L 2560,1220 r270 top value=49.9
R89 "CRCW040249R9FKED" 0402L 2420,1220 r270 top value=49.9
R90 "CRCW040249R9FKED" 0402L 2385,1220 r270 top value=49.9
R91 "MCR01MRTF1002" 0402L 3915,2480 r90 bottom value=10.0k
R92 "CRCW040275R0FKED" 0402 6445,2750 r270 bottom value=75.0
R93 "MCR01MRTF1002" 0402 2810,2930.15 r90 bottom value=10.0k
R94 "CRCW040275R0FKED" 0402 6380,2750 r270 bottom value=75.0
R95 "RC1206FR-071ML" 1206 6035,1955 r180 top value=1.00Meg
R96 "CRCW04020000Z0ED" 0402 2065,240 r90 top value=0
R97 "CRCW04020000Z0ED" 0402 2065,340 r90 top value=0
R98 "CRCW060391R0JNEA" 0603 3790,2605 r90 top value=91
R99 "CRCW020110K0FKED" 0201 4080,1012.01 r90 top value=10.0k
R100 "CRCW020110K0FKED" 0201 4510,1012.01 r90 top value=10.0k
R101 "RMCF0603ZT0R00" 0603L 4390,922.01 r270 top value=0
R102 "RMCF0603ZT0R00" 0603L 4120,922.01 r270 top value=0
R103 "CRCW020110K0FKED" 0201 4165.08,703 r90 top value=10.0k
R104 "CRCW020110K0FKED" 0201 4340,1012.01 r90 top value=10.0k
R105 "RMCF0603ZT0R00" 0603L 4120,922.01 r270 bottom value=0
R106 "RMCF0603ZT0R00" 0603L 4260,922.01 r270 bottom value=0
R107 "CRCW020110K0FKED" 0201 4345.08,703 r90 top value=10.0k
R108 "CRCW020110K0FKED" 0201 4390,1012.01 r90 top value=10.0k
R109 "RMCF0603ZT0R00" 0603L 4260,922.01 r270 top value=0
R110 "RMCF0603ZT0R00" 0603L 4200,922.01 r270 bottom value=0
R111 "CRCW020110K0FKED" 0201 4300.08,703 r90 top value=10.0k
R112 "CRCW020110K0FKED" 0201 4120,1012.01 r90 top value=10.0k
R113 "RMCF0603ZT0R00" 0603L 4200,922.01 r270 top value=0
R114 "RC0201FR-07100RL" 0201 2873,1515 r90 bottom value=100
R115 "RMCF0603ZT0R00" 0603L 4040,922.01 r270 top value=0
R116 "CRCW020110K0FKED" 0201 2700,1505 r180 bottom value=10.0k
R117 "CRCW020110K0FKED" 0201 4390.08,703 r90 top value=10.0k
R118 "CRCW020110K0FKED" 0201 4260,1012.01 r90 top value=10.0k
R119 "RMCF0603ZT0R00" 0603L 4040,922.01 r270 bottom value=0
R120 "RMCF0603ZT0R00" 0603L 3990,922.01 r270 top value=0
R121 "CRCW020110K0FKED" 0201 4120.08,703 r90 top value=10.0k
R122 "CRCW020110K0FKED" 0201 4200,1012.01 r90 top value=10.0k
R123 "RMCF0603ZT0R00" 0603L 3990,922.01 r270 bottom value=0
R124 "RCG060310K0FKEA" 0603L 5165,1100 r90 top value=10.0k
R125 "CRCW020110K0FKED" 0201 4255.08,703 r90 top value=10.0k
R126 "CRCW020110K0FKED" 0201 4040,1012.01 r90 top value=10.0k
R127 "RC0201JR-072K2L" 0201 4900,755 r180 top value=2.2k
R128 "CRCW020110K0FKED" 0201 4210.08,703 r90 top value=10.0k
R129 "CRCW020110K0FKED" 0201 3990,1012.01 r90 top value=10.0k
R131 "RC0201FR-074K99L" 0201 4485,2810 r180 bottom value=4.99k
R132 "RC0201FR-074K99L" 0201 4420,2810 r0 bottom value=4.99k
R133 "CRCW040222R0JNED" 0402 3225,665 r270 bottom value=22
R134 "CRCW040222R0JNED" 0402 2795,1430 r270 top value=22
R135 "CRCW040222R0JNED" 0402 2920,1385 r270 bottom value=22
R136 "CRCW060349R9FKEA" 0603L 5045,2400 r0 bottom value=49.9
R137 "CRCW060349R9FKEA" 0603L 5045,2310 r0 bottom value=49.9
R138 "CRCW060349R9FKEA" 0603L 5015,2535 r0 bottom value=49.9
R139 "CRCW060349R9FKEA" 0603L 5045,2580 r0 bottom value=49.9
R140 "CRCW060349R9FKEA" 0603L 5015,2625 r0 bottom value=49.9
R141 "CRCW060349R9FKEA" 0603L 5045,2670 r0 bottom value=49.9
R142 "CRCW060349R9FKEA" 0603L 5015,2445 r0 bottom value=49.9
R143 "CRCW060349R9FKEA" 0603L 5015,2355 r0 bottom value=49.9
R145 "MCR01MRTF1002" 0402L 2140,280 r180 top value=10.0k
R146 "CRCW02010000Z0ED" 0201 1235,1280 r180 top value=0
R147 "CRCW04022K49FKED" 0402 5400,1700 r90 top value=2.49k
R148 "CRCW06032K49FKEA" 0603 5275,1390 r180 top value=2.49k
R150 "CRCW120660R4FKEA" 1206 850,1175 r0 top value=60.4
R151 "CRCW120660R4FKEA" 1206 850,1025 r180 top value=60.4
SCL_CLK "TESTPOINT" PAD_3-2x1-9MM_SMD 4215,2805.92 r180 top
SDA_CLK "TESTPOINT" PAD_3-2x1-9MM_SMD 4040,2895.92 r0 top
T1 "HX1188FNLT" Pulse_HX1188FNLT 5895,2600 r0 top locked value=350uH
TP1 "PAD_1MM_SQUARE" PAD_1MM_SQUARE 2460,195 r0 top
TP2 "PAD_1MM_SQUARE" PAD_1MM_SQUARE 4455,2755 r90 top
TP19 "PAD_1MM_SQUARE" PAD_1MM_SQUARE 2180,2820 r90 top
TP50 "PAD_1MM_SQUARE" PAD_1MM_SQUARE 4105,2520 r180 top
TP51 "PAD_1MM_SQUARE" PAD_1MM_SQUARE 4200,2665 r180 top
TP52 "PAD_1MM_SQUARE" PAD_1MM_SQUARE 4795,2520 r180 top
TP53 "PAD_1MM_SQUARE" PAD_1MM_SQUARE 4700,2665 r180 top
TP54 "PAD_1MM_SQUARE" PAD_1MM_SQUARE 4530,2305 r180 top
TP55 "PAD_1MM_SQUARE" PAD_1MM_SQUARE 4410,2750 r0 bottom
TP56 "PAD_1MM_SQUARE" PAD_1MM_SQUARE 4490,2750 r0 bottom
TP57 "PAD_1MM_SQUARE" PAD_1MM_SQUARE 3980,2460 r0 bottom
TP58 "PAD_1MM_SQUARE" PAD_1MM_SQUARE 4685,2750 r0 bottom
TP59 "PAD_1MM_SQUARE" PAD_1MM_SQUARE 2585,450 r180 top
TP60 "PAD_1MM_SQUARE" PAD_1MM_SQUARE 2585,950 r180 top
TP61 "PAD_1MM_SQUARE" PAD_1MM_SQUARE 2940,615 r180 top
TP62 "PAD_1MM_SQUARE" PAD_1MM_SQUARE 2945,780 r180 top
TP63 "PAD_1MM_SQUARE" PAD_1MM_SQUARE 2155,330 r0 top
TP64 "TESTPOINT" PAD_1MM_SQUARE 2725,3170 r180 top
U1 "TCAN1042VDRBRQ1" DRB0008F 1360,852.6 r180 top
U2 "TCAN1042VDRBRQ1" DRB0008F 1350,1210 r180 top
U3 "TCAN1046VDMTRQ1" DMT0014A 1360,891 r180 top
U4 "TPD1E10B06QDPYRQ1" DPY0002A 5660,2800 r180 bottom
U5 "DP83848QSQX/NOPB" RTA0040A 5260,2500 r270 bottom
U6 "TPD1E10B06QDPYRQ1" DPY0002A 5660,2650 r180 bottom
U7 "TPD1E10B06QDPYRQ1" DPY0002A 5660,2460 r180 bottom
U8 "TPD1E10B06QDPYRQ1" DPY0002A 5660,2550 r180 bottom
U9 "DP83TC811RND" RND0036A 5495,1482 r90 top
U10 "TPD1E10B06QDPYRQ1" DPY0002A 5670,1500 r90 top
U11 "TPD1E10B06QDPYRQ1" DPY0002A 5670,1405 r270 top
U12 "CDCE913QPWRQ1" PW0014A_N 3700,2770.92 r0 top
U13 "DRA710CBD" CBD0538A 3500,1800 r180 top locked
U14 "MT41K64M16TW-107 AAT:J" 96-FBGA 2145,2205 r270 top locked
U15 "MT41K64M16TW-107 AAT:J" 96-FBGA 2145,1645 r270 top locked
U16 "S25FL256SAGMFB010" SOIC-16 4895,1000 r180 top
U17 "LM536253QRNLRQ1" RNL0022A_NV 1229.72,2885 r90 top
U18 "TPS61240IDRVRQ1" DRV0006A 1335,2005 r90 top
U19 "TPS51200QDRCRQ1" DRC0010J 2205,550 r270 top
U21 "TPD2E007DCKR" DCK0003A_N 620,687.6 r0 top
U23 "TPD2E007DCKR" DCK0003A_N 620,1097.6 r0 top
U24 "LM74610QDGKRQ1" DGK0008A_N 665,2430 r0 top
U25 "LP87332DRHDRQ1" RHD0028W 4450,2450 r90 top
U26 "LP873220RHDRQ1" RHD0028W 2800,700 r180 top
U27 "TPS22965QWDSGRQ1" DSG0008B 2750,3000 r90 top
Y1 "NX5032GA-25.000M-STD-CSK-4" NDK_NX5032GA 3700,3010.92 r180 top
ZZ1 "This Assembly Note is for PCB labels only" AssemblyNoteLabel 200,4100 r0 top
ZZ2 "These assemblies are ESD sensitive, ESD precautions shall be observed." AssemblyNote 200,4000 r0 top
ZZ3 "These assemblies must be clean and free from flux and all contaminants. Use of no clean flux is not acceptable." AssemblyNote 200,3900 r0 top
ZZ4 "These assemblies must comply with workmanship standards IPC-A-610 Class 2, unless otherwise specified." AssemblyNote 200,3800 r0 top

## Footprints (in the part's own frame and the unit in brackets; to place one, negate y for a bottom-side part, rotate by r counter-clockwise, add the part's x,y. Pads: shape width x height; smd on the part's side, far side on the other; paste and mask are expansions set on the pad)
96-FBGA [mm] "BGA, 96-Balls, Body 9x14mm, Pitch 0.8mm"
  round 0.41 smd: A1(-3.2,6) A2(-2.4,6) A3(-1.6,6) A7(1.6,6) A8(2.4,6) A9(3.2,6) B1(-3.2,5.2) B2(-2.4,5.2) B3(-1.6,5.2) B7(1.6,5.2) B8(2.4,5.2) B9(3.2,5.2) C1(-3.2,4.4) C2(-2.4,4.4) C3(-1.6,4.4) C7(1.6,4.4) C8(2.4,4.4) C9(3.2,4.4) D1(-3.2,3.6) D2(-2.4,3.6) D3(-1.6,3.6) D7(1.6,3.6) D8(2.4,3.6) D9(3.2,3.6) E1(-3.2,2.8) E2(-2.4,2.8) E3(-1.6,2.8) E7(1.6,2.8) E8(2.4,2.8) E9(3.2,2.8) F1(-3.2,2) F2(-2.4,2) F3(-1.6,2) F7(1.6,2) F8(2.4,2) F9(3.2,2) G1(-3.2,1.2) G2(-2.4,1.2) G3(-1.6,1.2) G7(1.6,1.2) G8(2.4,1.2) G9(3.2,1.2) H1(-3.2,0.4) H2(-2.4,0.4) H3(-1.6,0.4) H7(1.6,0.4) H8(2.4,0.4) H9(3.2,0.4) J1(-3.2,-0.4) J2(-2.4,-0.4) J3(-1.6,-0.4) J7(1.6,-0.4) J8(2.4,-0.4) J9(3.2,-0.4) K1(-3.2,-1.2) K2(-2.4,-1.2) K3(-1.6,-1.2) K7(1.6,-1.2) K8(2.4,-1.2) K9(3.2,-1.2) L1(-3.2,-2) L2(-2.4,-2) L3(-1.6,-2) L7(1.6,-2) L8(2.4,-2) L9(3.2,-2) M1(-3.2,-2.8) M2(-2.4,-2.8) M3(-1.6,-2.8) M7(1.6,-2.8) M8(2.4,-2.8) M9(3.2,-2.8) N1(-3.2,-3.6) N2(-2.4,-3.6) N3(-1.6,-3.6) N7(1.6,-3.6) N8(2.4,-3.6) N9(3.2,-3.6) P1(-3.2,-4.4) P2(-2.4,-4.4) P3(-1.6,-4.4) P7(1.6,-4.4) P8(2.4,-4.4) P9(3.2,-4.4) R1(-3.2,-5.2) R2(-2.4,-5.2) R3(-1.6,-5.2) R7(1.6,-5.2) R8(2.4,-5.2) R9(3.2,-5.2) T1(-3.2,-6) T2(-2.4,-6) T3(-1.6,-6) T7(1.6,-6) T8(2.4,-6) T9(3.2,-6)
  silkscreen extent -5.27,-7 4.5,7, body extent -4.5,-7 4.5,7, height 1.21
0201 [mm] "Data from Kemet datasheet CC101_COM dated 7/28/11"
  rect 0.46x0.42 smd mask+0.048: 1(-0.33,0) 2(0.33,0)
  body extent -0.31,-0.16 0.31,0.16, height 0.26
0201_033 [mm] "SMD, 2-Leads, Height 0.33mm"
  rect 0.46x0.42 smd mask+0.048: 1(-0.33,0) 2(0.33,0)
  body extent -0.31,-0.16 0.31,0.16, height 0.33
0402 [mm] "0402 from SM-752 data"
  rect 0.8x0.6 smd: 1(-0.6,0) 2(0.6,0)
  silkscreen extent -1.22,-0.52 1.22,0.52, body extent -0.55,-0.3 0.55,0.3, height 0.6
0402_065 [mm] "0402"
  rect 0.8x0.6 smd: 1(-0.6,0) 2(0.6,0)
  silkscreen extent -1.22,-0.52 1.22,0.52, body extent -0.55,-0.3 0.55,0.3, height 0.65
0402_070 [mil] "SMD, 2-Leads, Body 1.2x0.7mm, Height 0.7mm"
  rect 15x24 smd: 1(-20,0) 2(20,0)
  body extent -24,-14 24,14, height 28
0402L [mm] "0402 from SM-752 data"
  rect 0.6x0.5 smd: 1(-0.5,0) 2(0.5,0)
  body extent -0.55,-0.3 0.55,0.3, height 0.6
0508 [mm] "IPC nominal based on TDK C1220 type capacitors e4162_c.pdf"
  rect 0.8x2.25 smd: 1(-0.75,0) 2(0.75,0)
  silkscreen extent -1.44,-1.42 1.44,1.42, body extent -0.72,-1.1 0.72,1.1, height 1
0603 [mm] "0603 from SM-752 data"
  rect 1x0.95 smd: 1(-0.8,0) 2(0.8,0)
  silkscreen extent -1.52,-0.69 1.52,0.69, body extent -0.87,-0.47 0.87,0.47, height 1
0603L [mm] "0603 from SM-752 data"
  rect 0.8x0.85 smd: 1(-0.7,0) 2(0.7,0)
  silkscreen extent -0.07,-0.33 0.07,0.33, body extent -0.87,-0.47 0.87,0.47, height 1
0805_150 [mm] "0805 / 1.5 mm height"
  rect 1.15x1.45 smd: 1(-0.9,0) 2(0.9,0)
  silkscreen extent -0.1,-0.8 0.1,0.8, body extent -1.1,-0.72 1.1,0.72, height 1.5
0805_HV [mil] "0805 with 30mil clearance between pads"
  rect 50x63 smd: 1(-40,0) 2(40,0)
  silkscreen extent -74,-40 74,40, body extent -43,-29 43,29, height 57
0805L [mm] "0805 from SM-752 data"
  rect 1.1x1.4 smd: 1(-0.75,0) 2(0.75,0)
  body extent -1.1,-0.72 1.1,0.72, height 1.45
1206 [mm] "1206 from SM-752 data"
  rect 1.3x1.85 smd: 1(-1.45,0) 2(1.45,0)
  silkscreen extent -2.4,-1.21 2.4,1.21, body extent -1.7,-0.9 1.7,0.9, height 1.35
1206_180 [mm] "1206_180"
  rect 1.1x1.6 smd: 1(-1.7,0) 2(1.7,0)
  silkscreen extent -0.9,-1 0.9,1, body extent -1.75,-0.95 1.75,0.95, height 1.8
1206_180L [mm] "1206_180"
  rect 1.1x1.75 smd: 1(-1.35,0) 2(1.35,0)
  silkscreen extent -0.4,-0.77 0.4,0.77, body extent -1.75,-0.95 1.75,0.95, height 1.8
1206_190L [mm] "1206_190"
  rect 1.1x1.75 smd: 1(-1.35,0) 2(1.35,0)
  silkscreen extent -0.4,-0.77 0.4,0.77, body extent -1.75,-0.95 1.75,0.95, height 1.9
1210_150 [mm] "1210"
  rect 1.3x2.7 smd: 1(-1.45,0) 2(1.45,0)
  silkscreen extent -2.32,-1.57 2.32,1.57, body extent -1.7,-1.35 1.7,1.35, height 1.5
1210_270 [mm] "1210"
  rect 1.3x2.7 smd: 1(-1.45,0) 2(1.45,0)
  silkscreen extent -2.32,-1.57 2.32,1.57, body extent -1.7,-1.35 1.7,1.35, height 2.7
1210_270L [mm] "1210"
  rect 1.1x2.6 smd: 1(-1.35,0) 2(1.35,0)
  silkscreen extent -0.4,-1.2 0.4,1.2, body extent -1.7,-1.35 1.7,1.35, height 2.7
1210_280 [mm] "SMD, 2-Leads, Body 3.6x2.8mm, Height 2.8mm"
  rect 1.1x2.2 smd: 1(-1.65,0) 2(1.65,0)
  silkscreen extent -0.84,-1.4 0.84,1.4, body extent -1.8,-1.4 1.8,1.4, height 2.8
1812_254 [mm] "SMD, 2-Leads, Body 4.8x3.4mm"
  rect 1.6x3.4 smd: 1(-2,0) 2(2,0)
  silkscreen extent -0.8,-1.7 0.8,1.7, body extent -2.4,-1.7 2.4,1.7, height 2.54
6032-28 [mm] "Medium Density IPC based on Vishay Sprague 293D datasheet."
  rect 2.55x2.3 smd: 1(-2.375,0) 2(2.375,0)
  silkscreen extent -3.96,-1.75 3.2,1.82, body extent -3.15,-1.75 3.15,1.75, height 2.8
Abracon_ARJ012-110553 [mm] "Connector, RJ-45, R/A, TH"
  rect 1.4x1.4 hole 0.9: 1(-4.445,17.24)
  round 1.4 hole 0.9: 2(-3.175,19.78) 3(-1.905,17.24) 4(-0.635,19.78) 5(0.635,17.24) 6(1.905,19.78) 7(3.175,17.24) 8(4.445,19.78)
  round 3.25 hole 3.25 unplated mask+0: ALIGN1(-5.715,10.89) ALIGN2(5.715,10.89)
  round 2.1 hole 1.6: S1(-7.745,7.21) S2(7.745,7.21)
  silkscreen extent -7.94,1.4 7.94,22, body extent -7.94,0 7.94,21.27, height 13.45
AssemblyNote [mil] "Assembly Note"
AssemblyNoteLabel [mil] "Assembly Note for PCB Labels"
B82462G4 [mm] "EPCOS"
  rect 1.5x2.4 smd: 1(-2.75,0) 2(2.75,0)
  silkscreen extent -3.25,-3.25 3.25,3.25, body extent -3.15,-3.15 3.15,3.15, height 3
